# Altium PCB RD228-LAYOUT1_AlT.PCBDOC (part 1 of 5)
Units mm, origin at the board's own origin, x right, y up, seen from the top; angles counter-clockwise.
Board outline 130 x 73 mm, 4 copper layers (TOP, Mid-Layer 1, Mid-Layer 2, BOTTOM), stack 0.711 mm thick; 225 components, 171 nets, 818 pads, 538 vias.
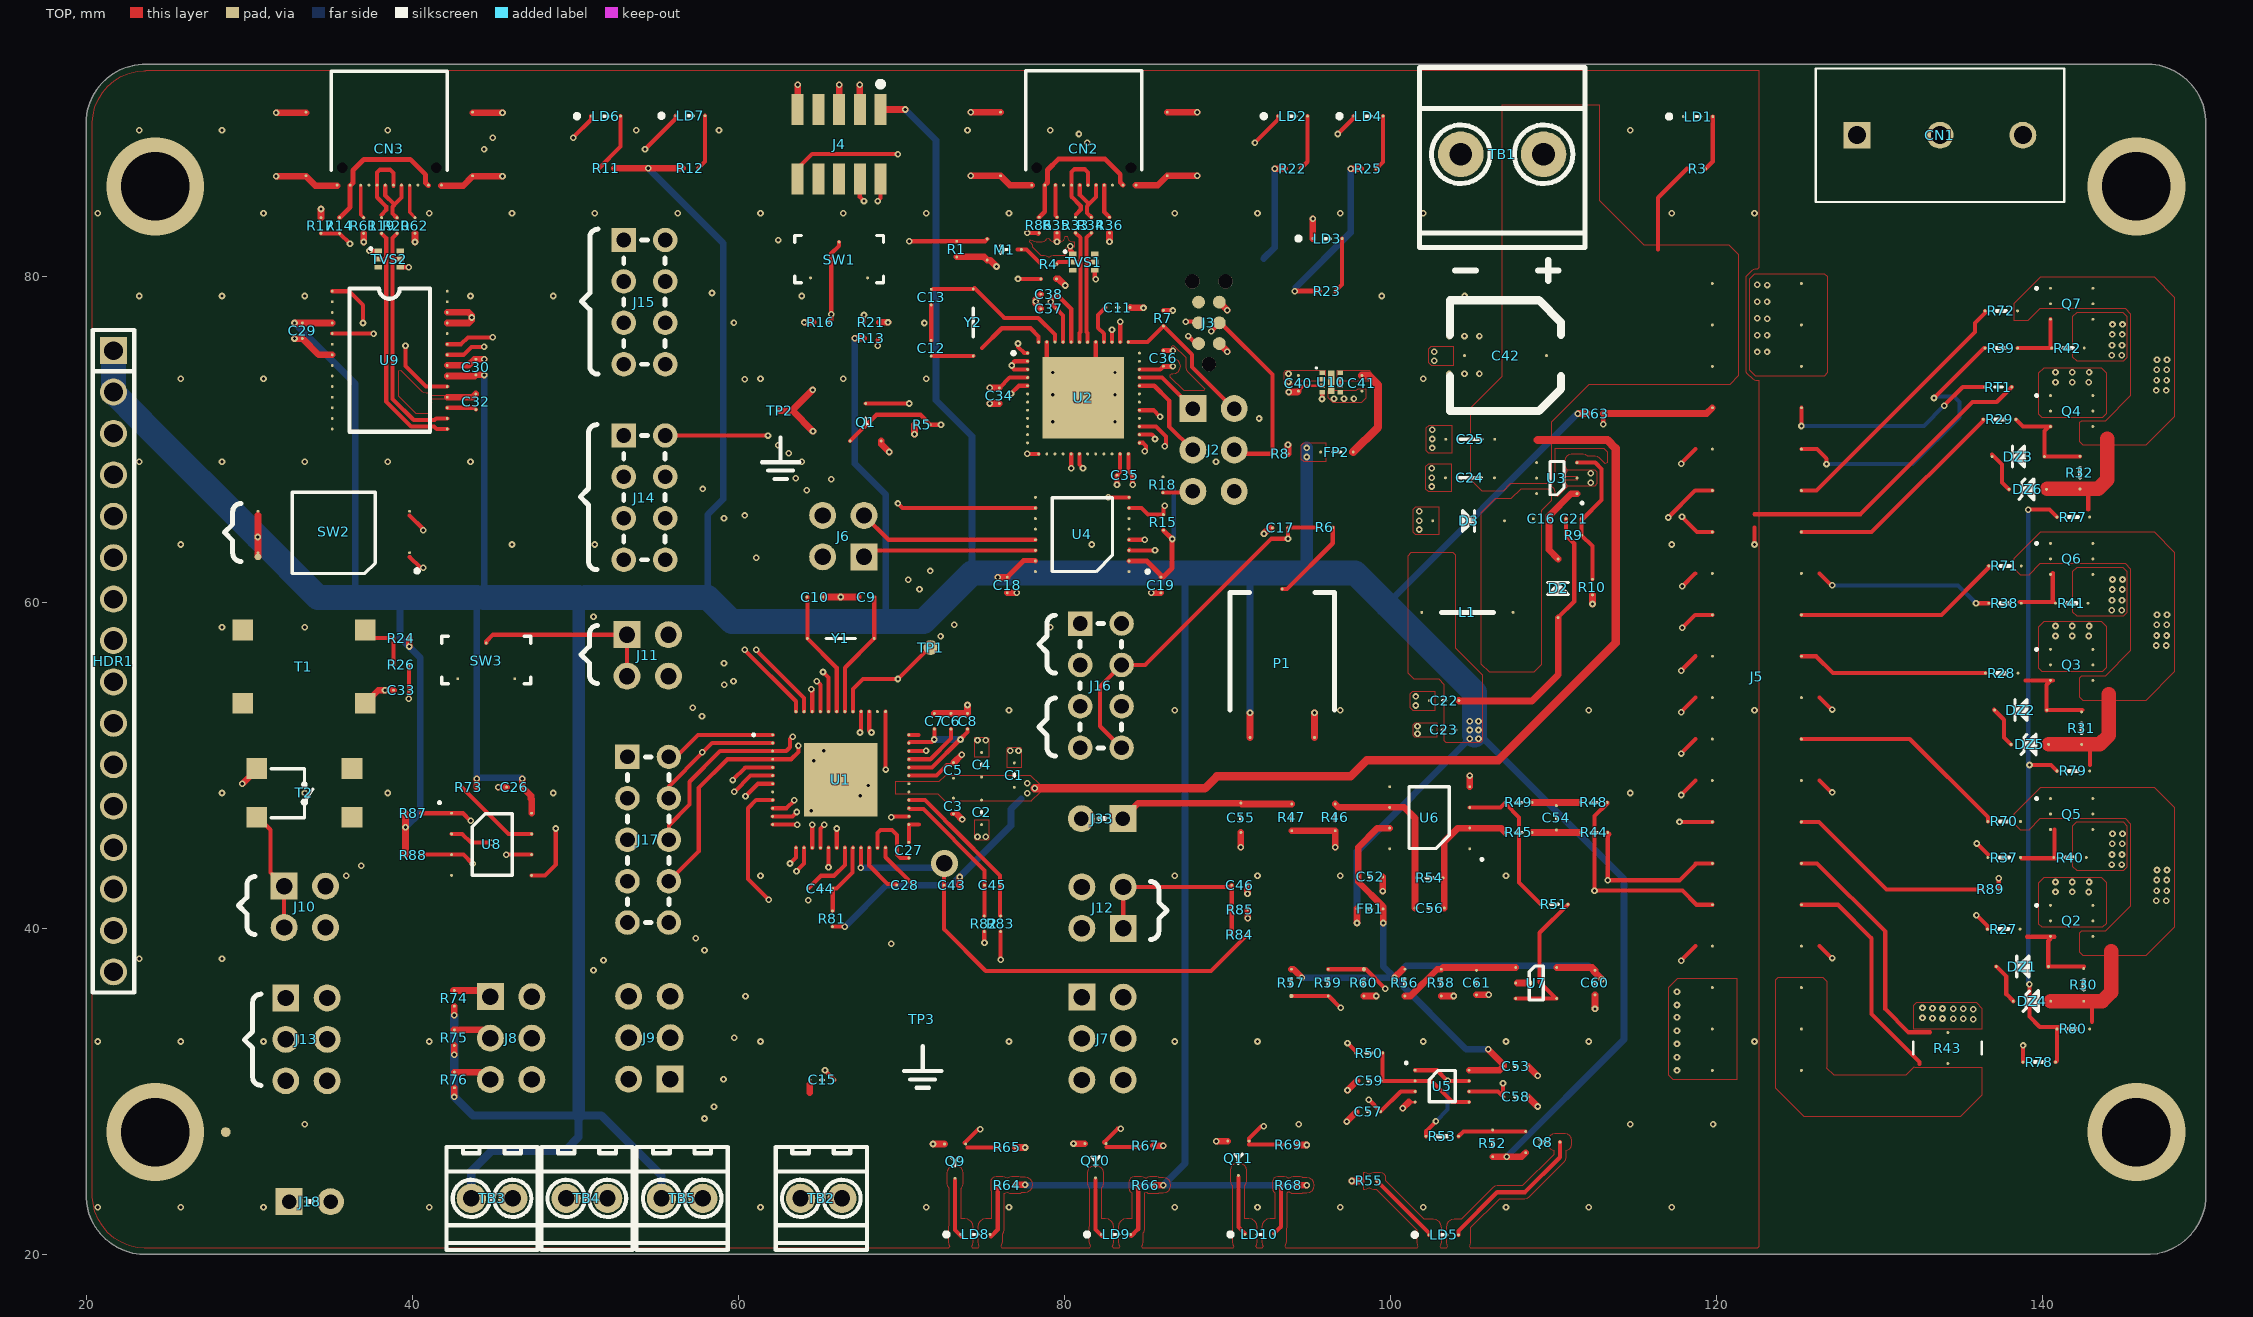
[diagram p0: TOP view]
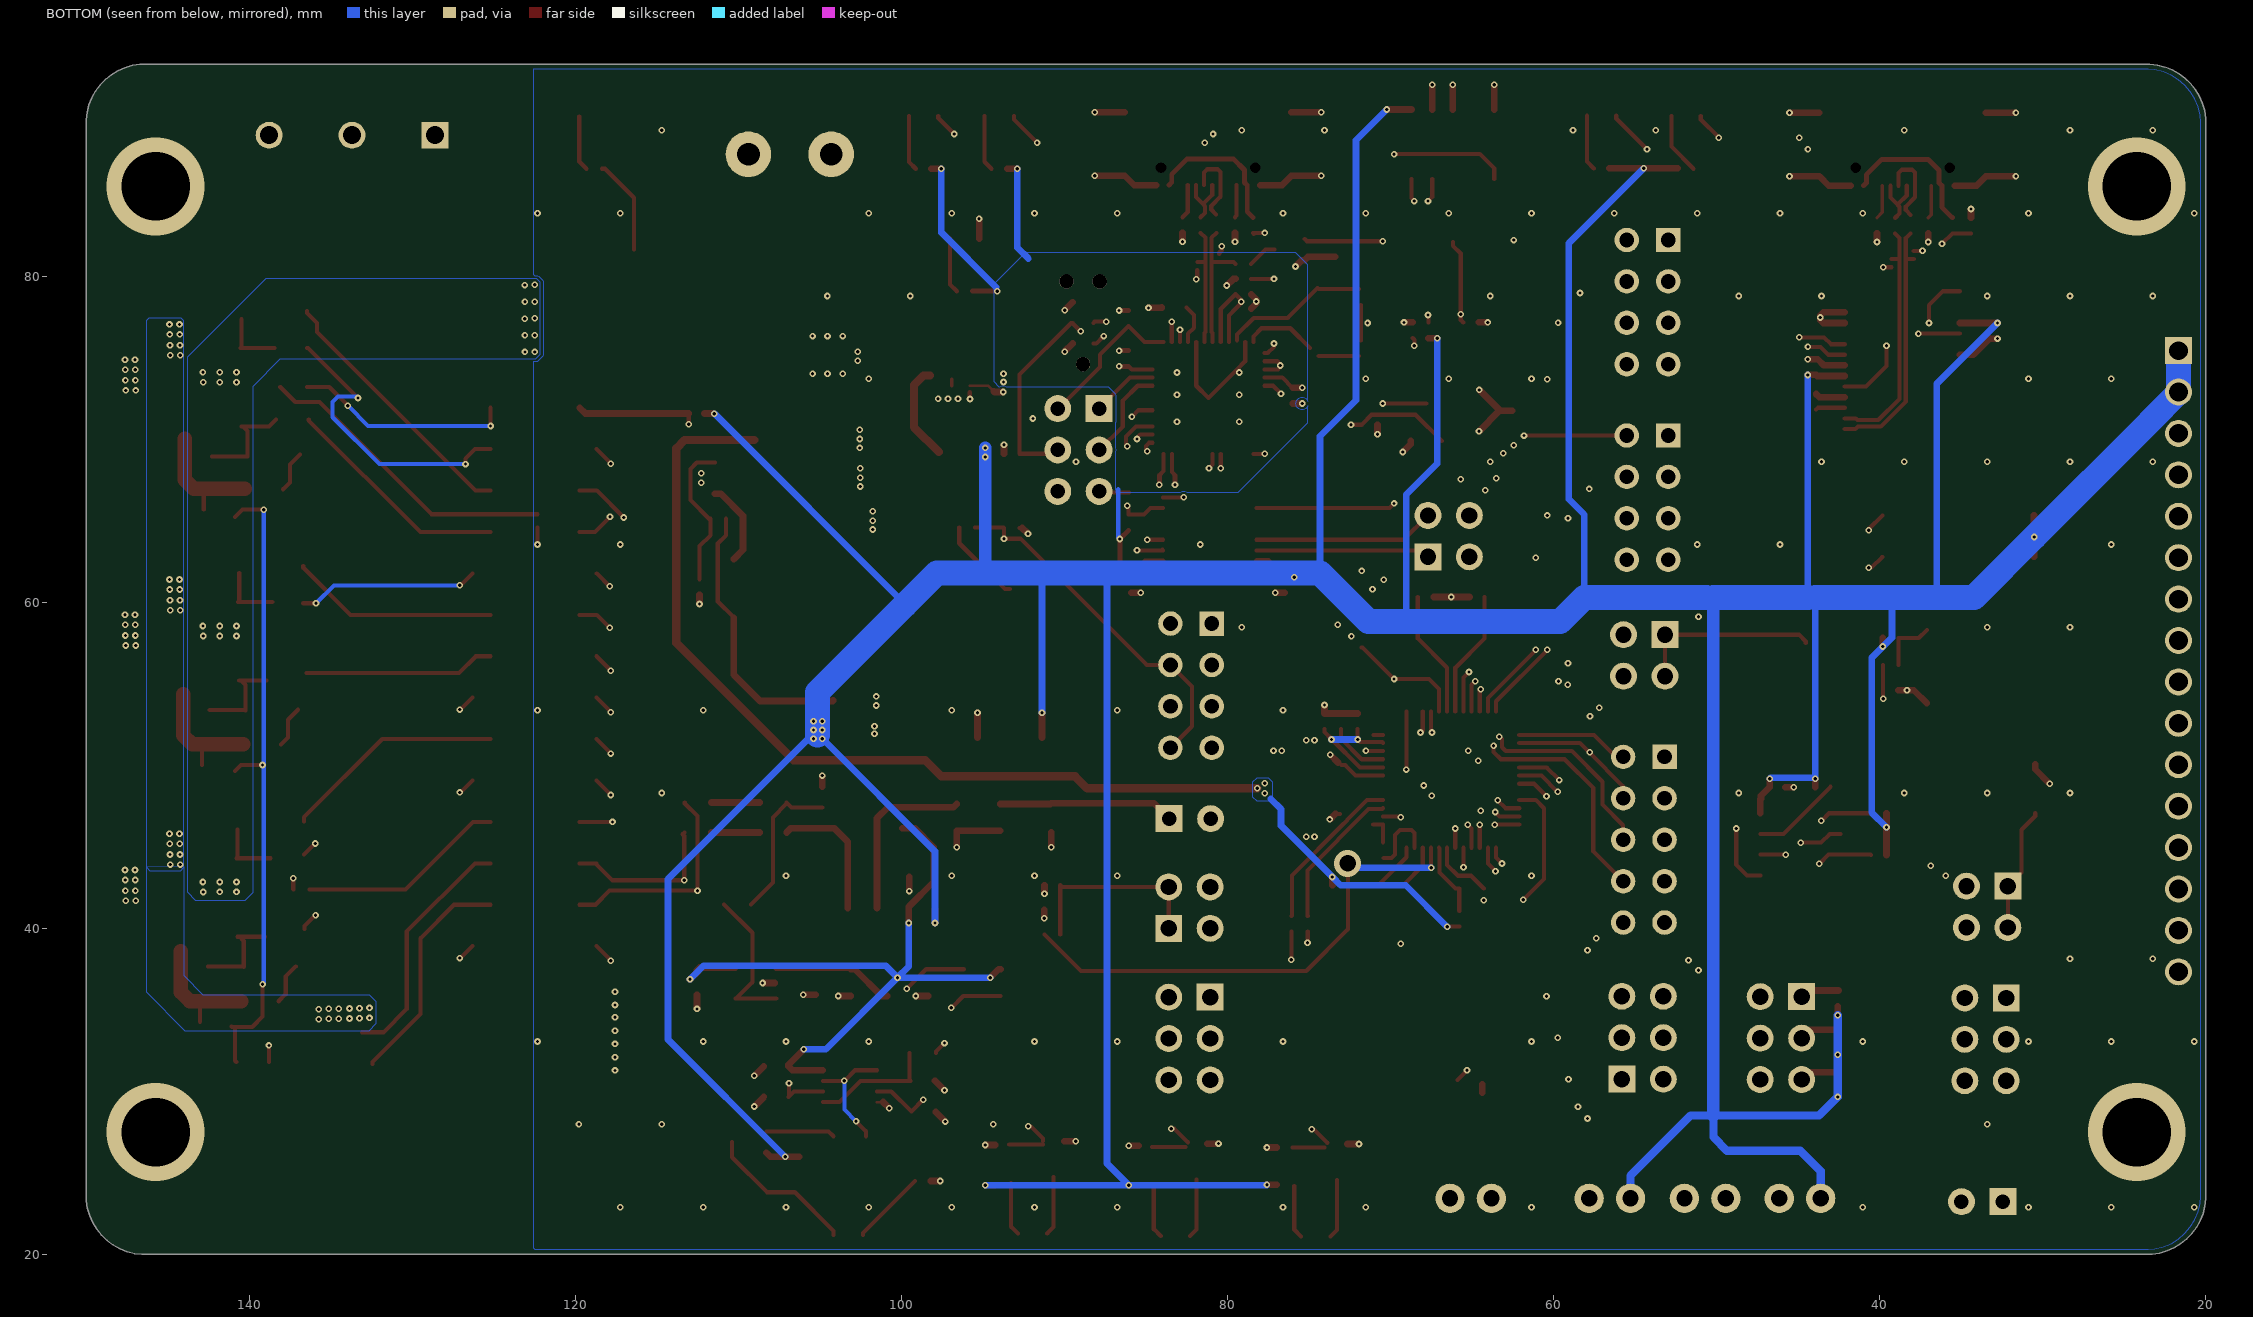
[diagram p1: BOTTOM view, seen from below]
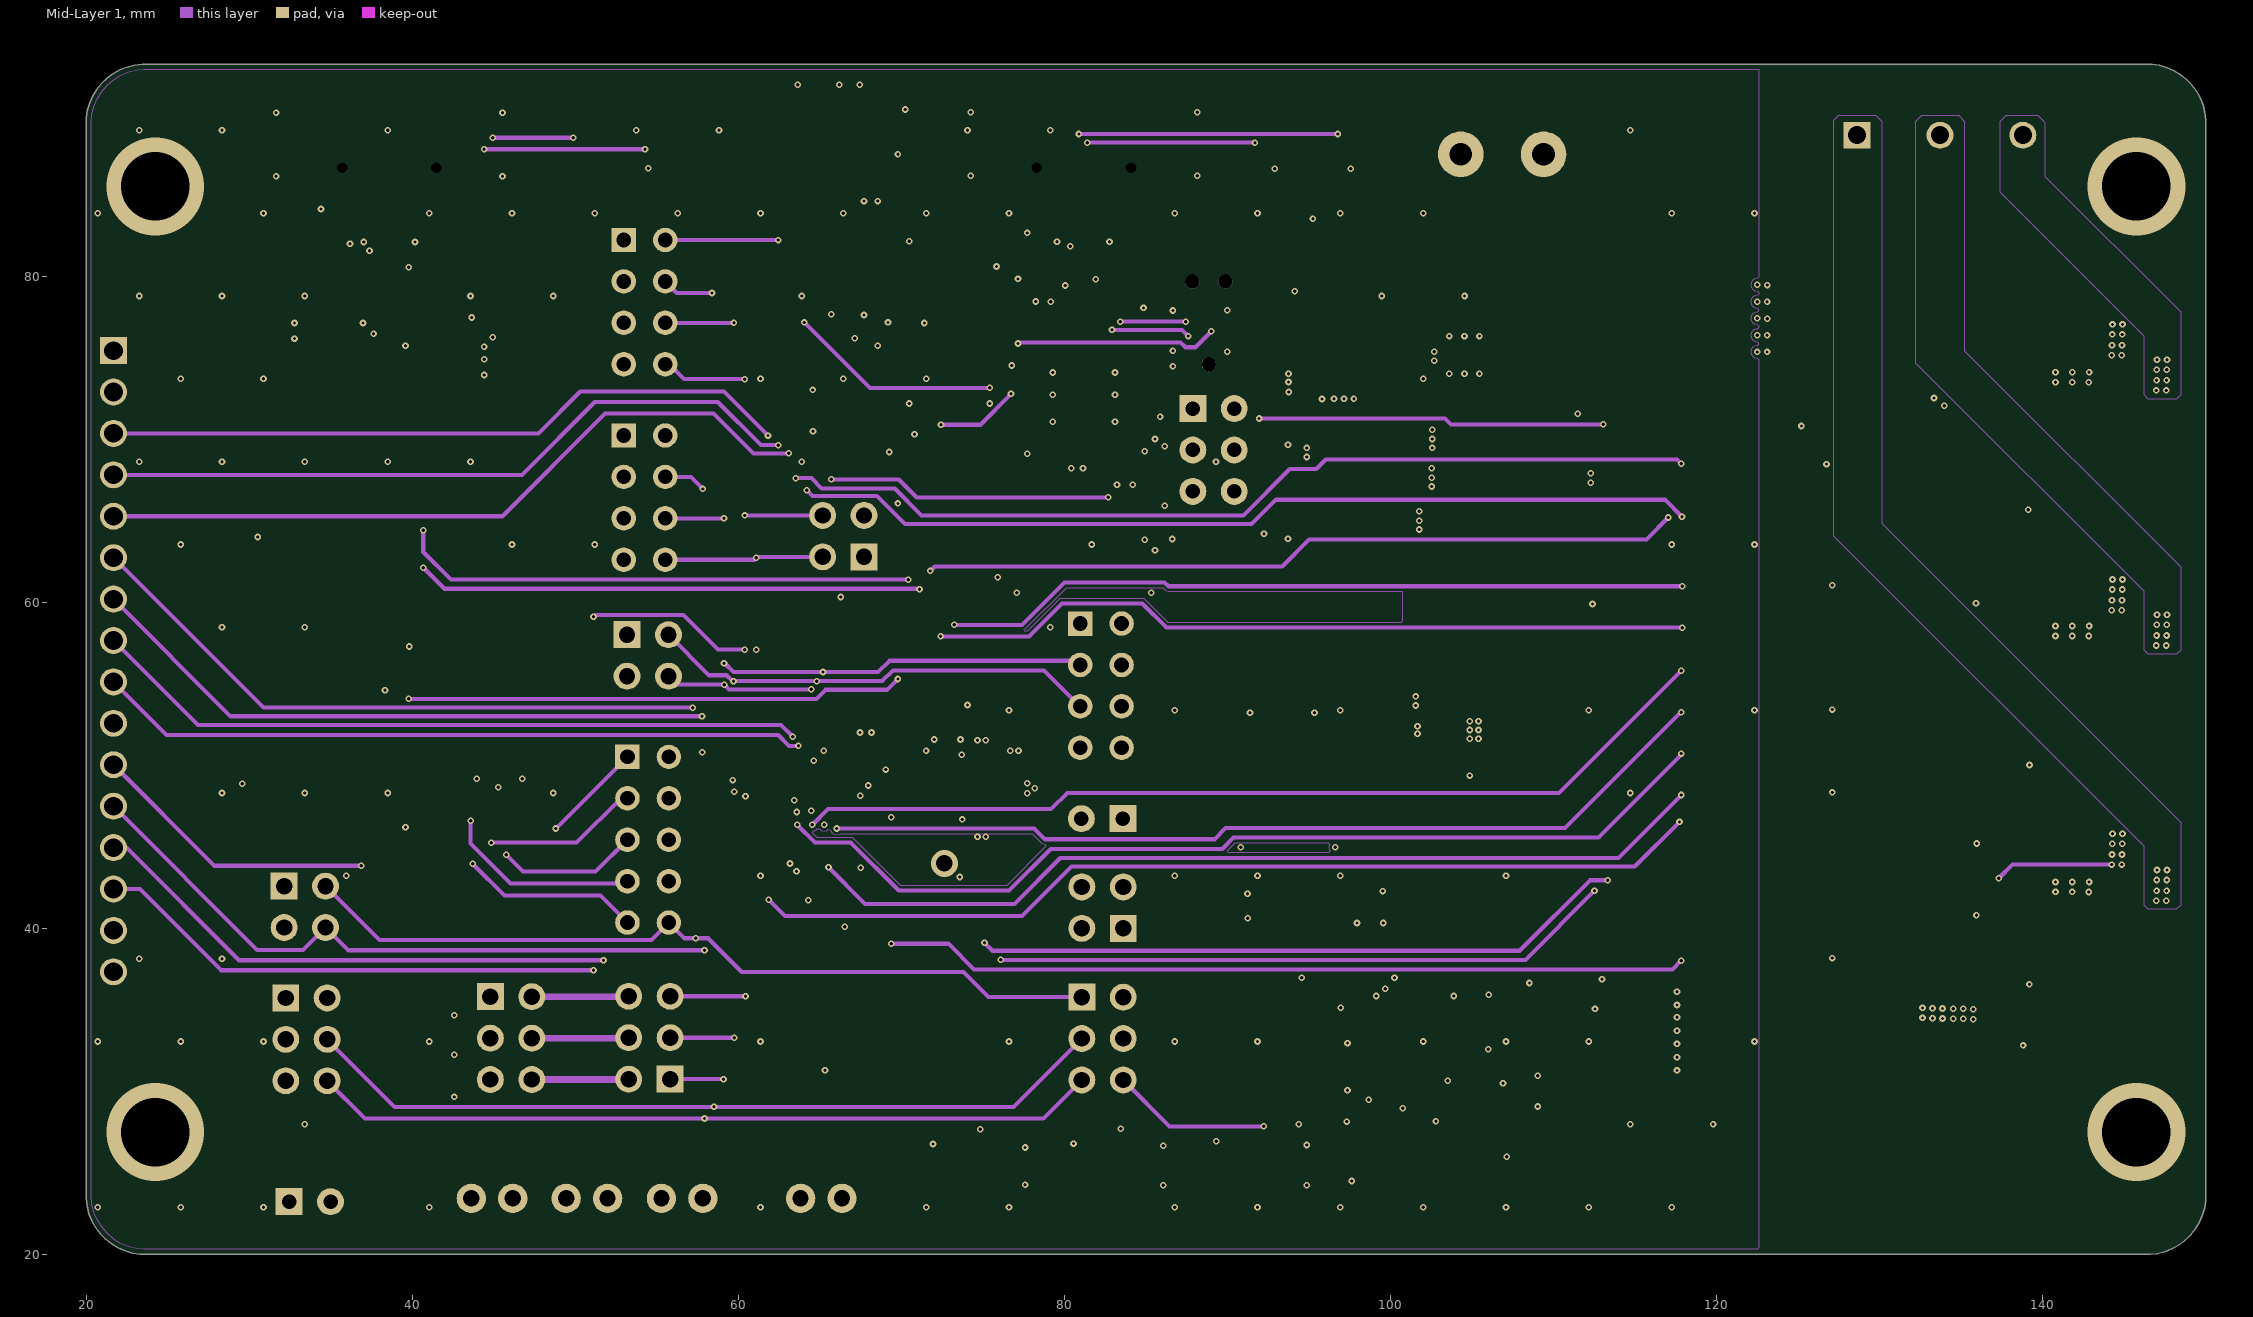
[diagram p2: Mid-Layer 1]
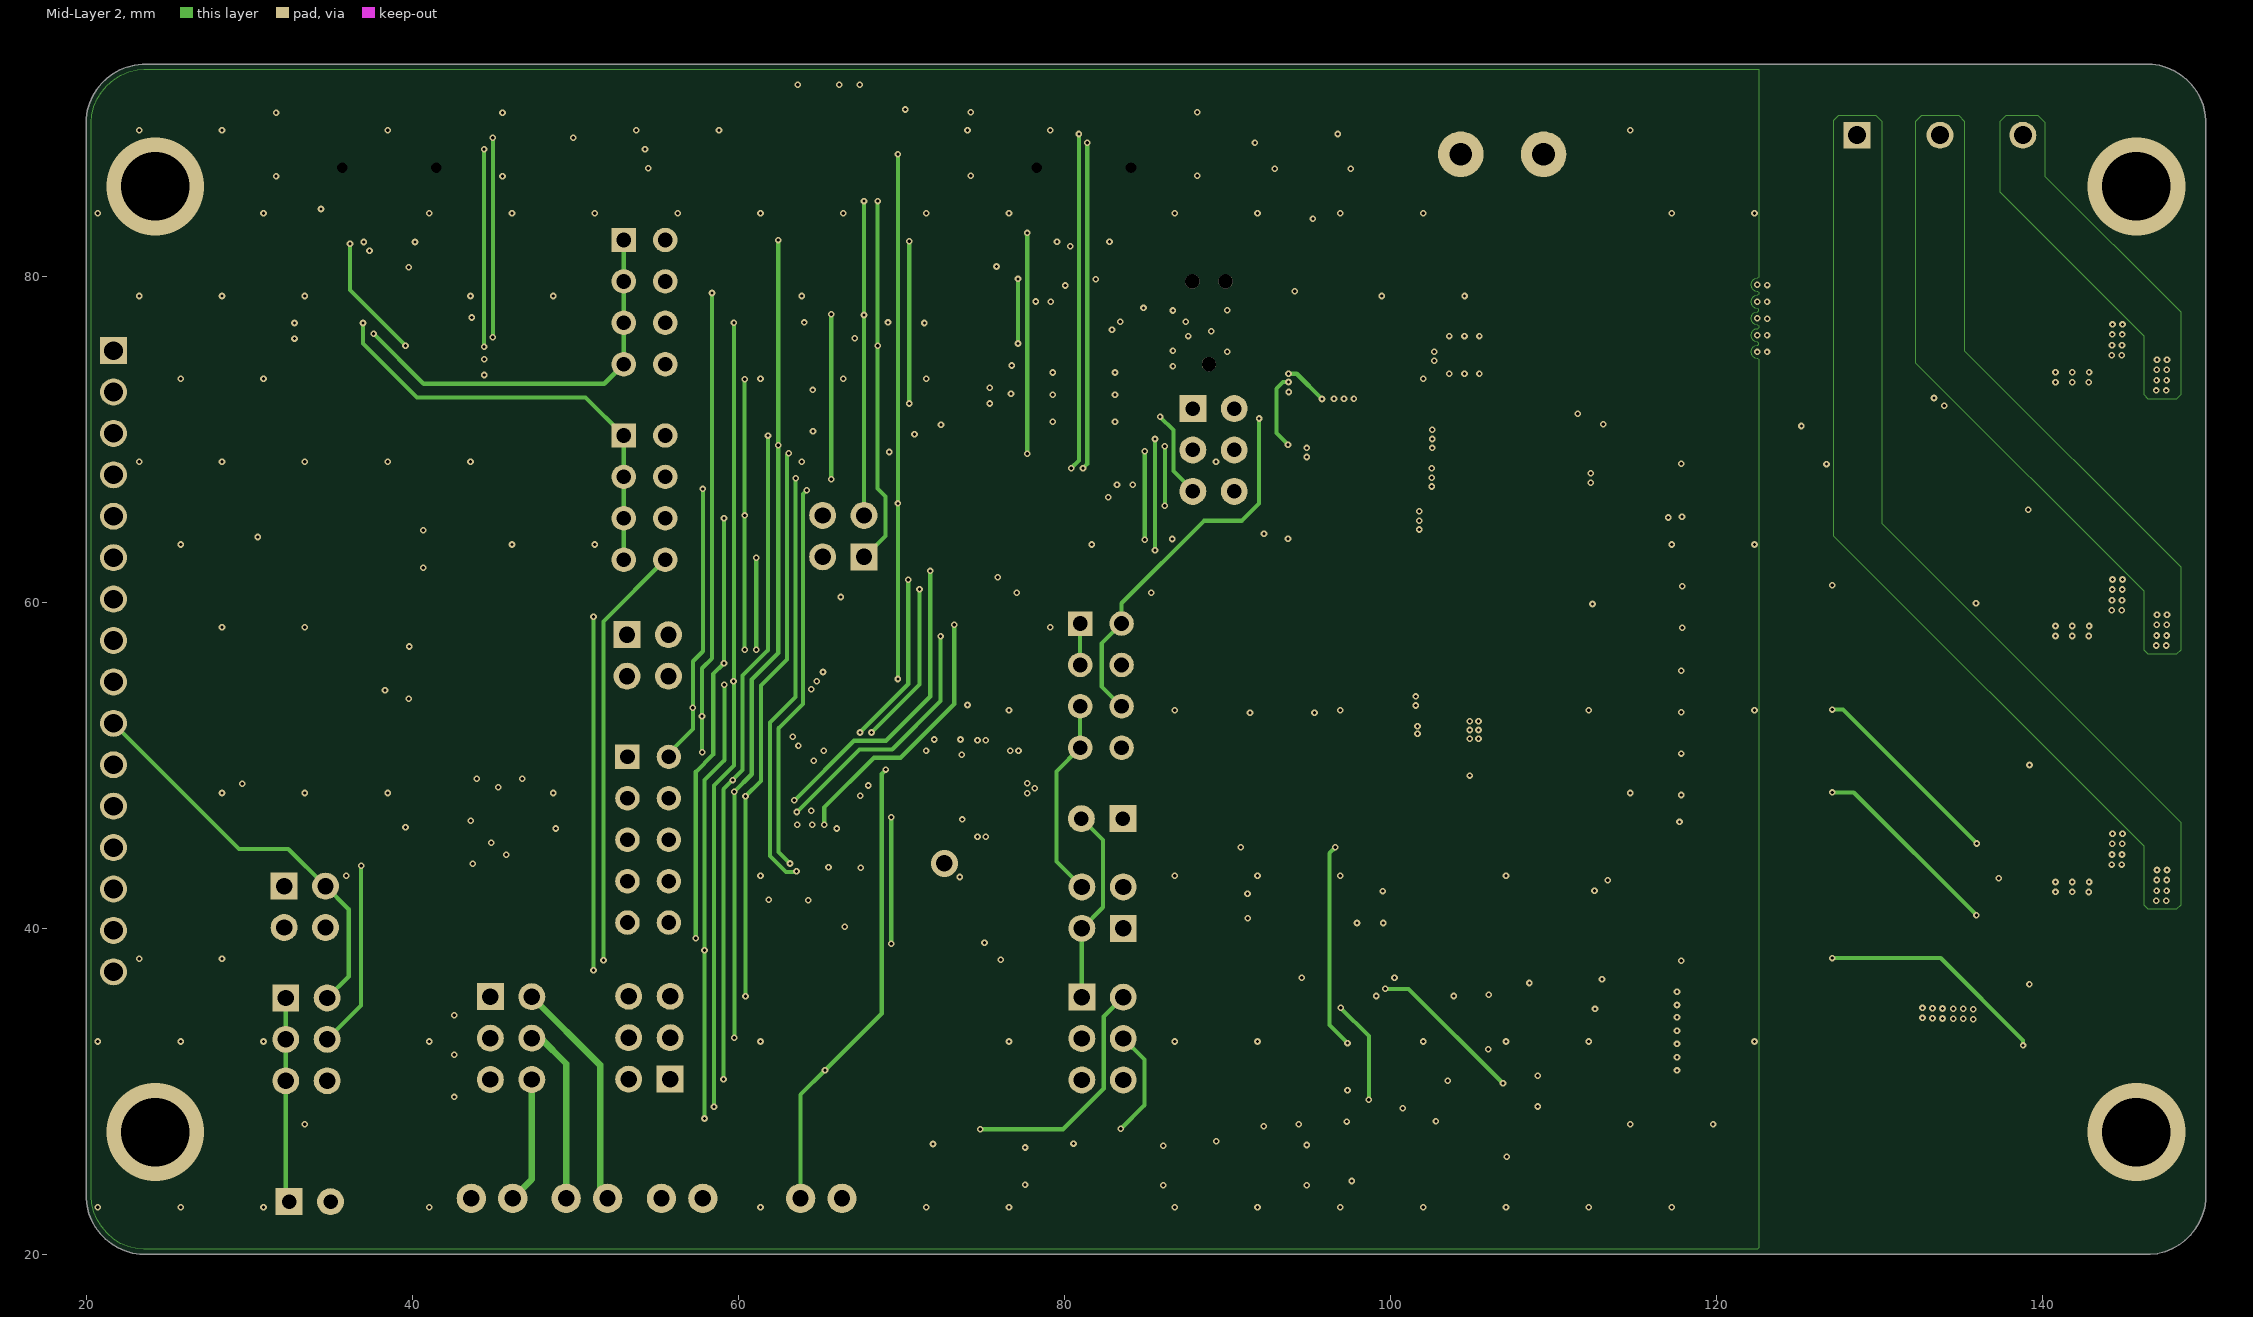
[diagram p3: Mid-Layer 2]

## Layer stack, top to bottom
Top Solder: solder mask 0.0102, Solder Resist, Dk 3.5
TOP: signal copper (thickness not stored)
Mid-Layer 1: signal copper 0.0356
Dielectric2: dielectric 0.32, FR-4, Dk 4.8
Mid-Layer 2: signal copper 0.0356
Dielectric3: dielectric 0.32, FR-4, Dk 4.8
BOTTOM: signal copper (thickness not stored)
Bottom Solder: solder mask 0.0102, Solder Resist, Dk 3.5

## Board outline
146.571,20 146.336,20.001 23.542,20.002 23.307,20.009 22.842,20.083 22.39,20.217 21.959,20.407 21.557,20.651 21.189,20.945 20.861,21.284 20.581,21.662 20.351,22.073 20.175,22.51 20.058,22.966 20,23.433 20.001,23.669 20.001,89.454 20.009,89.69 20.084,90.156 20.217,90.607 20.407,91.038 20.651,91.441 20.945,91.809 21.284,92.136 21.662,92.417 22.073,92.647 22.51,92.822 22.966,92.939 23.434,92.997 23.669,92.996 146.462,93.002 146.697,92.996 147.162,92.921 147.614,92.788 148.045,92.598 148.447,92.353 148.815,92.059 149.142,91.721 149.423,91.343 149.653,90.932 149.828,90.495 149.946,90.039 150.004,89.571 150.003,89.336 150.001,23.544 149.996,23.307 149.921,22.842 149.788,22.39 149.598,21.959 149.354,21.557 149.06,21.189 148.721,20.861 148.343,20.581 147.932,20.351 147.495,20.175 147.039,20.058

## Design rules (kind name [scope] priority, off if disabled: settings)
AssemblyTestPointUsage [All] p0: scope1count=1 scope1_0_kind=Board scope1_0_value=Board scope2count=1 scope2_0_kind=Board scope2_0_value=Board commentlength=0
AssemblyTestpoint [All] p0: scope1count=1 scope1_0_kind=Board scope1_0_value=Board scope2count=1 scope2_0_kind=Board scope2_0_value=Board commentlength=0
Clearance [All] p0: scope1count=1 scope1_0_kind=Board scope1_0_value=Board scope2count=1 scope2_0_kind=Board scope2_0_value=Board commentlength=0 gap=0.001
Clearance [All] p1: gap=0.001 ignorepadtopadclearanceinfootprint=TRUE except(0.15: Arc-Arc Arc-Track Arc-SMDPad Arc-THPad Arc-Via Arc-Fill Arc-Poly Arc-Region Arc-Text Track-Track Track-SMDPad Track-THPad Track-Via Track-Fill Track-Poly Track-Region Track-Text SMDPad-SMDPad SMDPad-THPad SMDPad-Via SMDPad-Fill SMDPad-Poly SMDPad-Region SMDPad-Text THPad-THPad THPad-Via THPad-Fill THPad-Poly THPad-Region THPad-Text Via-Via Via-Fill Via-Poly Via-Region Via-Text Fill-Fill Fill-Poly Fill-Region Fill-Text Poly-Poly Poly-Region Poly-Text Region-Region Region-Text Text-Text; 0.3: Arc-Hole Track-Hole SMDPad-Hole THPad-Hole Via-Hole Fill-Hole Poly-Hole Region-Hole Text-Hole)
ComponentClearance [All] p0: scope1count=1 scope1_0_kind=Board scope1_0_value=Board scope2count=1 scope2_0_kind=Board scope2_0_value=Board commentlength=0 gap=0.254 collisioncheckmode=3
DiffPairsRouting [All] p0: scope1count=1 scope1_0_kind=Board scope1_0_value=Board scope2count=1 scope2_0_kind=Board scope2_0_value=Board commentlength=0
FabricationTestPointUsage [All] p0: scope1count=1 scope1_0_kind=Board scope1_0_value=Board scope2count=1 scope2_0_kind=Board scope2_0_value=Board commentlength=0 valid=0 allowmultiple=FALSE
FabricationTestpoint [All] p0: scope1count=1 scope1_0_kind=Board scope1_0_value=Board scope2count=1 scope2_0_kind=Board scope2_0_value=Board commentlength=0 side=3 testpointundercomponent=TRUE minsize=1.016 maxsize=2.54 preferedsize=1.524 minholesize=0 maxholesize=1.016 preferedholesize=0.813 testpointgrid=0.025
FanoutControl Fanout_Default [All] p0: scope1count=1 scope1_0_kind=Board scope1_0_value=Board scope2count=1 scope2_0_kind=Board scope2_0_value=Board commentlength=30 // Fanout_Default (Default Rule)
FanoutControl Fanout_Small [All] p0 off: scope1count=1 scope1_0_kind=Board scope1_0_value=Board scope2count=1 scope2_0_kind=Board scope2_0_value=Board commentlength=84 // Protel DXP Scope 1 Expression Was: (CompPinCount < 5)   Fanout_Small (Default Rule)
FanoutControl Fanout_SOIC [All] p0 off: scope1count=1 scope1_0_kind=Board scope1_0_value=Board scope2count=1 scope2_0_kind=Board scope2_0_value=Board commentlength=71 // Protel DXP Scope 1 Expression Was: IsSOIC   Fanout_SOIC (Default Rule)
FanoutControl Fanout_LCC [All] p0 off: scope1count=1 scope1_0_kind=Board scope1_0_value=Board scope2count=1 scope2_0_kind=Board scope2_0_value=Board commentlength=69 // Protel DXP Scope 1 Expression Was: IsLCC   Fanout_LCC (Default Rule)
FanoutControl Fanout_BGA [All] p0 off: scope1count=1 scope1_0_kind=Board scope1_0_value=Board scope2count=1 scope2_0_kind=Board scope2_0_value=Board commentlength=69 // Protel DXP Scope 1 Expression Was: IsBGA   Fanout_BGA (Default Rule)
Height [All] p0: scope1count=1 scope1_0_kind=Board scope1_0_value=Board scope2count=1 scope2_0_kind=Board scope2_0_value=Board commentlength=0
HoleSize [All] p0: scope1count=1 scope1_0_kind=Board scope1_0_value=Board scope2count=1 scope2_0_kind=Board scope2_0_value=Board commentlength=0 absolutevalues=TRUE maxlimit=100 minlimit=0.001 maxpercent=80.000 minpercent=20.000
HoleSize [All] p1: absolutevalues=TRUE maxlimit=100 minlimit=0.001 maxpercent=80.000 minpercent=20.000
HoleToHoleClearance [All] p0: scope1count=1 scope1_0_kind=Board scope1_0_value=Board scope2count=1 scope2_0_kind=Board scope2_0_value=Board commentlength=0
HoleToHoleClearance [All] p1: gap=0.4 allowstackedmicrovias=FALSE
LayerPairs [All] p0: scope1count=1 scope1_0_kind=Board scope1_0_value=Board scope2count=1 scope2_0_kind=Board scope2_0_value=Board commentlength=0 enforce=TRUE
MinimumSolderMaskSliver [All] p0: scope1count=1 scope1_0_kind=Board scope1_0_value=Board scope2count=1 scope2_0_kind=Board scope2_0_value=Board commentlength=0
MinimumSolderMaskSliver [All] p1: minsoldermaskwidth=0.1
NetAntennae [All] p0: scope1count=1 scope1_0_kind=Board scope1_0_value=Board scope2count=1 scope2_0_kind=Board scope2_0_value=Board commentlength=0
NetAntennae [All] p1: netantennaetolerance=100
PasteMaskExpansion [All] p0: scope1count=1 scope1_0_kind=Board scope1_0_value=Board scope2count=1 scope2_0_kind=Board scope2_0_value=Board commentlength=0 expansion=0
PlaneClearance [All] p0: scope1count=1 scope1_0_kind=Board scope1_0_value=Board scope2count=1 scope2_0_kind=Board scope2_0_value=Board commentlength=0 clearance=0.001
PlaneClearance [All] p1: clearance=0.001
PlaneConnect [All] p0: scope1count=1 scope1_0_kind=Board scope1_0_value=Board scope2count=1 scope2_0_kind=Board scope2_0_value=Board commentlength=0 planeconnectstyle=Direct reliefexpansion=0.508 reliefentries=4 reliefconductorwidth=0.254 reliefairgap=0.254
PlaneConnect [All] p1: planeconnectstyle=Direct reliefexpansion=0.508 reliefentries=4 reliefconductorwidth=0.254 reliefairgap=0.254
PolygonConnect [All] p0: scope1count=1 scope1_0_kind=Board scope1_0_value=Board scope2count=1 scope2_0_kind=Board scope2_0_value=Board commentlength=0 connectstyle=Direct reliefconductorwidth=0.254 reliefentries=4 polygonreliefangle="90 Angle"
PolygonConnect [All] p1: connectstyle=Direct reliefconductorwidth=0.254 reliefentries=4 polygonreliefangle="90 Angle" airgapwidth=0.254
RoutingCorners [All] p0: scope1count=1 scope1_0_kind=Board scope1_0_value=Board scope2count=1 scope2_0_kind=Board scope2_0_value=Board commentlength=0 cornerstyle=45-Degree minsetback=2.54 maxsetback=2.54
RoutingLayers [All] p0: scope1count=1 scope1_0_kind=Board scope1_0_value=Board scope2count=1 scope2_0_kind=Board scope2_0_value=Board commentlength=0 top layer=Automatic mid layer 1=Automatic mid layer 2=Automatic bottom layer=Automatic
RoutingPriority [All] p0: scope1count=1 scope1_0_kind=Board scope1_0_value=Board scope2count=1 scope2_0_kind=Board scope2_0_value=Board commentlength=0
RoutingTopology [All] p0: scope1count=1 scope1_0_kind=Board scope1_0_value=Board scope2count=1 scope2_0_kind=Board scope2_0_value=Board commentlength=0 topology=Shortest
RoutingVias [All] p0: scope1count=1 scope1_0_kind=Board scope1_0_value=Board scope2count=1 scope2_0_kind=Board scope2_0_value=Board commentlength=0 holewidth=0.1 width=0.1 viastyle="Through Hole" minholewidth=0.001 minwidth=0.001 maxholewidth=100 maxwidth=100
RoutingVias [All] p1: holewidth=0.1 width=0.1 viastyle="Through Hole" minholewidth=0.001 minwidth=0.001 maxholewidth=100 maxwidth=100
ShortCircuit [All] p0: scope1count=1 scope1_0_kind=Board scope1_0_value=Board scope2count=1 scope2_0_kind=Board scope2_0_value=Board commentlength=0 allowed=FALSE
ShortCircuit [All] p0: scope1count=1 scope1_0_kind=Board scope1_0_value=Board scope2count=1 scope2_0_kind=Board scope2_0_value=Board commentlength=0 allowed=FALSE
SilkToBoardRegionClearance [All] p0: scope1count=1 scope1_0_kind=Board scope1_0_value=Board scope2count=1 scope2_0_kind=Board scope2_0_value=Board commentlength=0
SilkToSilkClearance [All] p0: scope1count=1 scope1_0_kind=Board scope1_0_value=Board scope2count=1 scope2_0_kind=Board scope2_0_value=Board commentlength=0
SilkToSilkClearance [All] p1: silktosilkclearance=0.001
SilkToSolderMaskClearance [All] p0 off: scope1count=1 scope1_0_kind=Board scope1_0_value=Board scope2count=1 scope2_0_kind=Board scope2_0_value=Board commentlength=44 // Protel DXP Scope 1 Expression Was: IsPad
SilkToSolderMaskClearance [IsPad] p1: minsilkscreentomaskgap=0 clearancetoexposedcopper=TRUE
SolderMaskExpansion [All] p0: scope1count=1 scope1_0_kind=Board scope1_0_value=Board scope2count=1 scope2_0_kind=Board scope2_0_value=Board commentlength=0 expansion=0.001
SolderMaskExpansion [All] p1: expansion=0.001
UnRoutedNet [All] p0: scope1count=1 scope1_0_kind=Board scope1_0_value=Board scope2count=1 scope2_0_kind=Board scope2_0_value=Board commentlength=0
UnpouredPolygon [All] p0: scope1count=1 scope1_0_kind=Board scope1_0_value=Board scope2count=1 scope2_0_kind=Board scope2_0_value=Board commentlength=0
Width [All] p0: scope1count=1 scope1_0_kind=Board scope1_0_value=Board scope2count=1 scope2_0_kind=Board scope2_0_value=Board commentlength=0 maxlimit=1000 minlimit=2539.975 preferedwidth=0
Width [All] p1: maxlimit=1000 minlimit=2539.975 preferedwidth=0 toplayer_minwidth=0 midlayer1_minwidth=0 midlayer2_minwidth=0 bottomlayer_minwidth=0 minimp=50.000000 maximp=50.000000 favimp=50.000000
22 further rules are at their usual default settings.

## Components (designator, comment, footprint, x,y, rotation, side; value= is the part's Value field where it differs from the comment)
C1 "CAPC1608X55N-0603-NoOverlay" CAPC1608X55N-0603-NoOverlay 76.925,49.397 r0 top
C2 "CAPC1608X55N-0603-NoOverlay" CAPC1608X55N-0603-NoOverlay 74.919,47.111 r180 top
C3 "CAPC1005X55N-0402-NoOverlay" CAPC1005X55N-0402-NoOverlay 73.191,47.502 r180 top
C4 "CAPC1608X55N-0603-NoOverlay" CAPC1608X55N-0603-NoOverlay 74.919,50.032 r0 top
C5 "CAPC1005X55N-0402-NoOverlay" CAPC1005X55N-0402-NoOverlay 73.195,49.687 r0 top
C6 "CAPC1005X55N-0402-NoOverlay" CAPC1005X55N-0402-NoOverlay 73.039,52.699 r0 top
C7 "CAPC1005X55N-0402-NoOverlay" CAPC1005X55N-0402-NoOverlay 72.023,52.699 r0 top
C8 "CAPC1005X55N-0402-NoOverlay" CAPC1005X55N-0402-NoOverlay 74.055,52.699 r0 top
C9 "CAPC1005X55N-0402-NoOverlay" CAPC1005X55N-0402-NoOverlay 67.832,60.319 r90 top
C10 "CAPC1005X55N-0402-NoOverlay" CAPC1005X55N-0402-NoOverlay 64.682,60.319 r270 top
C11 "CAPC1608X55N-0603-NoOverlay" CAPC1608X55N-0603-NoOverlay 83.275,78.073 r270 top
C12 "CAPC1005X55N-0402-NoOverlay" CAPC1005X55N-0402-NoOverlay 71.828,75.575 r0 top
C13 "CAPC1005X55N-0402-NoOverlay" CAPC1005X55N-0402-NoOverlay 71.828,78.708 r180 top
C15 "CAPC1608X55N-0603-NoOverlay" CAPC1608X55N-0603-NoOverlay 65.14,30.702 r90 top
C16 "CAPC1005X55N-0402-NoOverlay" CAPC1005X55N-0402-NoOverlay 109.234,65.119 r90 top
C17 "CAPC1005X55N-0402-NoOverlay" CAPC1005X55N-0402-NoOverlay 93.232,64.561 r270 top
C18 "CAPC1005X55N-0402-NoOverlay" CAPC1005X55N-0402-NoOverlay 76.493,61.055 r0 top
C19 "CAPC1005X55N-0402-NoOverlay" CAPC1005X55N-0402-NoOverlay 85.917,61.055 r0 top
C21 "CAPC1005X55N-0402-NoOverlay" CAPC1005X55N-0402-NoOverlay 111.241,65.119 r270 top
C22 "CAPC2013X100N-0805-NoOverlay" CAPC2013X100N-0805-NoOverlay 103.29,53.969 r90 top
C23 "CAPC1608X55N-0603-NoOverlay" CAPC1608X55N-0603-NoOverlay 103.253,52.165 r270 top
C24 "CAPC3216X140N-1206-NoOverlay" CAPC3216X140N-1206-NoOverlay 104.865,67.63 r0 top
C25 "CAPC3216X140N-1206-NoOverlay" CAPC3216X140N-1206-NoOverlay 104.889,69.996 r0 top
C26 "CAPC1005X55N-0402-NoOverlay" CAPC1005X55N-0402-NoOverlay 46.27,48.66 r90 top
C27 "CAPC1005X55N-0402-NoOverlay" CAPC1005X55N-0402-NoOverlay 70.458,44.799 r0 top
C28 "CAPC1005X55N-0402-NoOverlay" CAPC1005X55N-0402-NoOverlay 70.197,42.645 r270 top
C29 "CAPC1005X55N-0402-NoOverlay" CAPC1005X55N-0402-NoOverlay 33.263,76.651 r0 top
C30 "CAPC1005X55N-0402-NoOverlay" CAPC1005X55N-0402-NoOverlay 43.905,74.423 r180 top
C32 "CAPC1005X55N-0402-NoOverlay" CAPC1005X55N-0402-NoOverlay 43.905,72.29 r180 top
C33 "CAPC1005X55N-0402-NoOverlay" CAPC1005X55N-0402-NoOverlay 39.333,54.604 r270 top
C34 "CAPC1005X55N-0402-NoOverlay" CAPC1005X55N-0402-NoOverlay 76.011,72.663 r0 top
C35 "CAPC1005X55N-0402-NoOverlay" CAPC1005X55N-0402-NoOverlay 83.707,67.786 r90 top
C36 "CAPC1005X55N-0402-NoOverlay" CAPC1005X55N-0402-NoOverlay 86.069,74.949 r180 top
C37 "CAPC1005X55N-0402-NoOverlay" CAPC1005X55N-0402-NoOverlay 79.033,77.997 r270 top
C38 "CAPC1005X55N-0402-NoOverlay" CAPC1005X55N-0402-NoOverlay 79.033,78.886 r270 top
C40 "CAPC1005X55N-0402-NoOverlay" CAPC1005X55N-0402-NoOverlay 94.35,73.425 r180 top
C41 "CAPC1005X55N-0402-NoOverlay" CAPC1005X55N-0402-NoOverlay 98.245,73.425 r180 top
C42 "CAPAE660X550D700DD185L260N" CAPAE660X550D700DD185L260N 107.05,75.127 r180 top
C43 "CAPC1005X55N-0402-NoOverlay" CAPC1005X55N-0402-NoOverlay 73.087,42.64 r90 top
C44 "CAPC1608X55N-0603-NoOverlay" CAPC1608X55N-0603-NoOverlay 65.038,42.437 r90 top
C45 "CAPC1005X55N-0402-NoOverlay" CAPC1005X55N-0402-NoOverlay 75.579,42.64 r270 top
C46 "CAPC1005X55N-0402-NoOverlay" CAPC1005X55N-0402-NoOverlay 90.743,42.64 r270 top
C52 "CAPC1608X55N-0603-NoOverlay" CAPC1608X55N-0603-NoOverlay 98.769,43.148 r270 top
C53 "CAPC1608X55N-0603-NoOverlay" CAPC1608X55N-0603-NoOverlay 107.685,31.541 r270 top
C54 "CAPC1608X55N-0603-NoOverlay" CAPC1608X55N-0603-NoOverlay 110.174,46.781 r0 top
C55 "CAPC2013X100N-0805-NoOverlay" CAPC2013X100N-0805-NoOverlay 90.819,46.781 r180 top
C56 "CAPC2013X100N-0805-NoOverlay" CAPC2013X100N-0805-NoOverlay 102.401,41.243 r90 top
C57 "CAPC1608X55N-0603-NoOverlay" CAPC1608X55N-0603-NoOverlay 98.642,28.763 r90 top
C58 "CAPC1608X55N-0603-NoOverlay" CAPC1608X55N-0603-NoOverlay 107.685,29.661 r270 top
C59 "CAPC1608X55N-0603-NoOverlay" CAPC1608X55N-0603-NoOverlay 98.693,30.652 r90 top
C60 "CAPC1608X55N-0603-NoOverlay" CAPC1608X55N-0603-NoOverlay 112.536,36.671 r180 top
C61 "CAPC1608X55N-0603-NoOverlay" CAPC1608X55N-0603-NoOverlay 105.272,36.671 r180 top
CN1 "SCREW_TERMINAL_3P_5.08" SCREW_TERMINAL_3P_5.08 133.694,88.64 r0 top
CN2 "USB-C_SMD_16P-NoOverlay_r1" USB-C_SMD_16P-NoOverlay_r1 81.192,87.776 r180 top
CN3 "USB-C_SMD_16P-NoOverlay_r1" USB-C_SMD_16P-NoOverlay_r1 38.597,87.776 r180 top
D2 "SOD3716X135N-NoOverlay" SOD3716X135N-NoOverlay 110.275,60.852 r270 top
D3 "DIOM5127X229N-SOD128-NoOverlay" DIOM5127X229N-SOD128-NoOverlay 104.789,64.992 r180 top
DZ1 "SFLAT300P360X150X100-2N" SFLAT300P360X150X100-2N 138.749,37.658 r0 top
DZ2 "SFLAT300P360X150X100-2N" SFLAT300P360X150X100-2N 138.647,53.381 r0 top
DZ3 "SFLAT300P360X150X100-2N" SFLAT300P360X150X100-2N 138.495,68.929 r0 top
DZ4 "XCUZ230P125X250X100-2N" XCUZ230P125X250X100-2N 139.34,35.532 r0 top
DZ5 "XCUZ230P125X250X100-2N" XCUZ230P125X250X100-2N 139.206,51.28 r0 top
DZ6 "XCUZ230P125X250X100-2N" XCUZ230P125X250X100-2N 139.079,66.924 r0 top
FB1 "INDC1608X95N-0603-NOOVERLAY" INDC1608X95N-0603-NOOVERLAY 98.744,41.193 r0 top
FP2 "INDC2213X140N-0805-NOOVERLAY" INDC2213X140N-0805-NOOVERLAY 96.712,69.209 r0 top
HDR1 "HM1X16_-_Male" HM1X16_-_Male 21.68,56.382 r0 top
J2 "JUMPER-FLD2X3" JUMPER-FLD2X3 87.873,71.876 r0 top
J3 "TC2030NL_r1" TC2030NL_r1 88.863,77.134 r90 top
J4 "HM2X5-SMD-1.27" HM2X5-SMD-1.27 66.181,88.09 r270 top
J5 "HM254P2x20-SMD" HM254P2x20-SMD 122.467,55.417 r0 top
J6 "HM2X2" HM2X2 66.439,64.053 r180 top
J7 "HM2X3" HM2X3 82.335,33.242 r0 top
J8 "HM2X3" HM2X3 46.064,33.268 r0 top
J9 "HM2X3" HM2X3 54.548,33.293 r180 top
J10 "HM2X2" HM2X2 33.415,41.32 r0 top
J11 "HM2X2" HM2X2 54.446,56.737 r0 top
J12 "HM2X2" HM2X2 82.335,41.269 r180 top
J13 "HM2X3" HM2X3 33.517,33.192 r0 top
J14 "HM2X4-NoOverlay" HM2X4-NoOverlay 54.243,66.415 r0 top
J15 "HM2X4-NoOverlay" HM2X4-NoOverlay 54.243,78.404 r0 top
J16 "HM2X4-NoOverlay" HM2X4-NoOverlay 82.234,54.883 r0 top
J17 "HM2X5-NoOverlay" HM2X5-NoOverlay 54.472,45.434 r0 top
J18 "HM1x2-NoOverlay" HM1x2-NoOverlay 33.72,23.235 r0 top
J33 "HM1x2-NoOverlay" HM1x2-NoOverlay 82.31,46.73 r180 top
L1 "IND_8x8x4-NoOverlay" IND_8x8x4-NoOverlay 104.713,59.379 r180 top
LD1 "DIOGREENC2013X120N-0805-NoOverlay" DIOGREENC2013X120N-0805-NoOverlay 118.861,89.783 r270 top
LD2 "DIOGREENC2013X120N-0805-NoOverlay" DIOGREENC2013X120N-0805-NoOverlay 94.005,89.808 r270 top
LD3 "DIOGREENC2013X120N-0805-NoOverlay" DIOGREENC2013X120N-0805-NoOverlay 96.128,82.3 r270 top
LD4 "DIOGREENC2013X120N-0805-NoOverlay" DIOGREENC2013X120N-0805-NoOverlay 98.642,89.808 r270 top
LD5 "DIOREDC2013X120N-0805-NoOverlay" DIOREDC2013X120N-0805-NoOverlay 103.265,21.203 r0 top
LD6 "DIOYELLOWC2013X120N-0805-NoOverlay" DIOYELLOWC2013X120N-0805-NoOverlay 51.881,89.808 r0 top
LD7 "DIOREDC2013X120N-0805-NoOverlay" DIOREDC2013X120N-0805-NoOverlay 57.062,89.834 r0 top
LD8 "DIOREDC2013X120N-0805-NoOverlay" DIOREDC2013X120N-0805-NoOverlay 74.538,21.228 r0 top
LD9 "DIOREDC2013X120N-0805-NoOverlay" DIOREDC2013X120N-0805-NoOverlay 83.165,21.228 r0 top
LD10 "DIOREDC2013X120N-0805-NoOverlay" DIOREDC2013X120N-0805-NoOverlay 91.962,21.228 r0 top
M1 "SOT65P210X100-3N-NoOverlay" SOT65P210X100-3N-NoOverlay 76.313,81.629 r0 top
P1 "N6R" N6R 93.359,56.255 r0 top
Q1 "SOT95P240X110-3N-NoOverlay" SOT95P240X110-3N-NoOverlay 67.811,71.038 r90 top
Q2 "TSOP6F95P220X290X80-6N" TSOP6F95P220X290X80-6N 141.772,40.459 r270 top
Q3 "TSOP6F95P220X290X80-6N" TSOP6F95P220X290X80-6N 141.772,56.157 r270 top
Q4 "TSOP6F95P220X290X80-6N" TSOP6F95P220X290X80-6N 141.772,71.724 r270 top
Q5 "TSOP6F95P220X290X80-6N" TSOP6F95P220X290X80-6N 141.772,47.01 r270 top
Q6 "TSOP6F95P220X290X80-6N" TSOP6F95P220X290X80-6N 141.772,62.656 r270 top
Q7 "TSOP6F95P220X290X80-6N" TSOP6F95P220X290X80-6N 141.772,78.302 r270 top
Q8 "SOT65P210X100-3N-NoOverlay" SOT65P210X100-3N-NoOverlay 109.336,26.892 r0 top
Q9 "SOT65P210X100-3N-NoOverlay" SOT65P210X100-3N-NoOverlay 73.293,25.724 r270 top
Q10 "SOT65P210X100-3N-NoOverlay" SOT65P210X100-3N-NoOverlay 81.904,25.749 r270 top
Q11 "SOT65P210X100-3N-NoOverlay" SOT65P210X100-3N-NoOverlay 90.667,25.902 r270 top
R1 "RESC1005X40N-0402-NOOVERLAY" RESC1005X40N-0402-NOOVERLAY 73.395,81.657 r180 top
R3 "RESC1005X40N-0402-NOOVERLAY" RESC1005X40N-0402-NOOVERLAY 118.835,86.582 r270 top
R4 "RESC1005X40N-0402-NOOVERLAY" RESC1005X40N-0402-NOOVERLAY 79.033,80.74 r270 top
R5 "RESC1005X40N-0402-NOOVERLAY" RESC1005X40N-0402-NOOVERLAY 71.286,70.885 r90 top
R6 "RESC1005X40N-0402-NOOVERLAY" RESC1005X40N-0402-NOOVERLAY 95.973,64.586 r90 top
R7 "RESC1005X40N-0402-NOOVERLAY" RESC1005X40N-0402-NOOVERLAY 86.069,77.413 r0 top
R8 "RESC1005X40N-0402-NOOVERLAY" RESC1005X40N-0402-NOOVERLAY 93.232,69.107 r90 top
R9 "RESC1005X40N-0402-NOOVERLAY" RESC1005X40N-0402-NOOVERLAY 111.241,64.103 r270 top
R10 "RESC1005X40N-0402-NOOVERLAY" RESC1005X40N-0402-NOOVERLAY 112.384,60.928 r180 top
R11 "RESC1005X40N-0402-NOOVERLAY" RESC1005X40N-0402-NOOVERLAY 51.906,86.608 r90 top
R12 "RESC1005X40N-0402-NOOVERLAY" RESC1005X40N-0402-NOOVERLAY 57.062,86.608 r270 top
R13 "RESC1005X40N-0402-NOOVERLAY" RESC1005X40N-0402-NOOVERLAY 68.162,76.194 r90 top
R14 "RESC1005X40N-0402-NOOVERLAY" RESC1005X40N-0402-NOOVERLAY 35.549,83.103 r180 top
R15 "RESC1005X40N-0402-NOOVERLAY" RESC1005X40N-0402-NOOVERLAY 86.069,64.893 r0 top
R16 "RESC1005X40N-0402-NOOVERLAY" RESC1005X40N-0402-NOOVERLAY 65.063,77.159 r270 top
R17 "RESC1005X40N-0402-NOOVERLAY" RESC1005X40N-0402-NOOVERLAY 34.406,83.103 r0 top
R18 "RESC1005X40N-0402-NOOVERLAY" RESC1005X40N-0402-NOOVERLAY 86.044,67.202 r0 top
R19 "RESC1005X40N-0402-NOOVERLAY" RESC1005X40N-0402-NOOVERLAY 38.127,83.103 r0 top
R20 "RESC1005X40N-0402-NOOVERLAY" RESC1005X40N-0402-NOOVERLAY 39.067,83.103 r0 top
R21 "RESC1005X40N-0402-NOOVERLAY" RESC1005X40N-0402-NOOVERLAY 68.162,77.159 r90 top
R22 "RESC1005X40N-0402-NOOVERLAY" RESC1005X40N-0402-NOOVERLAY 93.994,86.582 r90 top
R23 "RESC1005X40N-0402-NOOVERLAY" RESC1005X40N-0402-NOOVERLAY 96.128,79.074 r270 top
R24 "RESC1005X40N-0402-NOOVERLAY" RESC1005X40N-0402-NOOVERLAY 39.333,57.804 r90 top
R25 "RESC1005X40N-0402-NOOVERLAY" RESC1005X40N-0402-NOOVERLAY 98.642,86.582 r90 top
R26 "RESC1005X40N-0402-NOOVERLAY" RESC1005X40N-0402-NOOVERLAY 39.333,56.153 r270 top
R27 "RESC2013X38N-0805-NOOVERLAY" RESC2013X38N-0805-NOOVERLAY 137.606,39.951 r90 top
R28 "RESC2013X38N-0805-NOOVERLAY" RESC2013X38N-0805-NOOVERLAY 137.479,55.648 r90 top
R29 "RESC2013X38N-0805-NOOVERLAY" RESC2013X38N-0805-NOOVERLAY 137.352,71.215 r90 top
R30 "RESC2013X38N-0805-NOOVERLAY" RESC2013X38N-0805-NOOVERLAY 142.508,36.53 r180 top
R31 "RESC2013X38N-0805-NOOVERLAY" RESC2013X38N-0805-NOOVERLAY 142.381,52.278 r180 top
R32 "RESC2013X38N-0805-NOOVERLAY" RESC2013X38N-0805-NOOVERLAY 142.279,67.945 r180 top
R33 "RESC1005X40N-0402-NOOVERLAY" RESC1005X40N-0402-NOOVERLAY 80.684,83.128 r0 top
R34 "RESC1005X40N-0402-NOOVERLAY" RESC1005X40N-0402-NOOVERLAY 81.65,83.128 r0 top
R35 "RESC1005X40N-0402-NOOVERLAY" RESC1005X40N-0402-NOOVERLAY 79.541,83.128 r180 top
R36 "RESC1005X40N-0402-NOOVERLAY" RESC1005X40N-0402-NOOVERLAY 82.767,83.128 r180 top
R37 "RESC2013X38N-0805-NOOVERLAY" RESC2013X38N-0805-NOOVERLAY 137.631,44.342 r90 top
R38 "RESC2013X38N-0805-NOOVERLAY" RESC2013X38N-0805-NOOVERLAY 137.682,59.938 r90 top
R39 "RESC2013X38N-0805-NOOVERLAY" RESC2013X38N-0805-NOOVERLAY 137.453,75.584 r90 top
R40 "RESC2013X38N-0805-NOOVERLAY" RESC2013X38N-0805-NOOVERLAY 141.67,44.342 r270 top
R41 "RESC2013X38N-0805-NOOVERLAY" RESC2013X38N-0805-NOOVERLAY 141.771,59.938 r270 top
R42 "RESC2013X38N-0805-NOOVERLAY" RESC2013X38N-0805-NOOVERLAY 141.543,75.584 r270 top
R43 "RES1508wide" RES1508wide 134.177,32.658 r90 top
R44 "RESC1508X55N-0603-NOOVERLAY" RESC1508X55N-0603-NOOVERLAY 112.493,45.88 r270 top
R45 "RESC1508X55N-0603-NOOVERLAY" RESC1508X55N-0603-NOOVERLAY 107.862,45.88 r270 top
R46 "RESC1508X55N-0603-NOOVERLAY" RESC1508X55N-0603-NOOVERLAY 96.61,46.806 r0 top
R47 "RESC1508X55N-0603-NOOVERLAY" RESC1508X55N-0603-NOOVERLAY 93.943,46.806 r180 top
R48 "RESC1508X55N-0603-NOOVERLAY" RESC1508X55N-0603-NOOVERLAY 112.467,47.72 r270 top
R49 "RESC1508X55N-0603-NOOVERLAY" RESC1508X55N-0603-NOOVERLAY 107.862,47.72 r270 top
R50 "RESC1508X55N-0603-NOOVERLAY" RESC1508X55N-0603-NOOVERLAY 98.693,32.353 r90 top
R51 "RESC1508X55N-0603-NOOVERLAY" RESC1508X55N-0603-NOOVERLAY 110.054,41.472 r270 top
R52 "RESC1508X55N-0603-NOOVERLAY" RESC1508X55N-0603-NOOVERLAY 106.262,26.816 r0 top
R53 "RESC2013X38N-0805-NOOVERLAY" RESC2013X38N-0805-NOOVERLAY 103.173,27.248 r90 top
R54 "RESC1508X55N-0603-NOOVERLAY" RESC1508X55N-0603-NOOVERLAY 102.401,43.098 r270 top
R55 "RESC1005X40N-0402-NOOVERLAY" RESC1005X40N-0402-NOOVERLAY 98.69,24.505 r270 top
R56 "RESC1508X55N-0603-NOOVERLAY" RESC1508X55N-0603-NOOVERLAY 100.877,36.671 r180 top
R57 "RESC1508X55N-0603-NOOVERLAY" RESC1508X55N-0603-NOOVERLAY 93.918,36.671 r180 top
R58 "RESC1508X55N-0603-NOOVERLAY" RESC1508X55N-0603-NOOVERLAY 103.113,36.671 r180 top
R59 "RESC1508X55N-0603-NOOVERLAY" RESC1508X55N-0603-NOOVERLAY 96.178,36.671 r0 top
R60 "RESC1508X55N-0603-NOOVERLAY" RESC1508X55N-0603-NOOVERLAY 98.363,36.671 r180 top
R61 "RESC1005X40N-0402-NOOVERLAY" RESC1005X40N-0402-NOOVERLAY 37.022,83.103 r180 top
R62 "RESC1005X40N-0402-NOOVERLAY" RESC1005X40N-0402-NOOVERLAY 40.171,83.103 r180 top
R63 "RESC1005X40N-0402-NOOVERLAY" RESC1005X40N-0402-NOOVERLAY 112.561,71.571 r90 top
R64 "RESC1005X40N-0402-NOOVERLAY" RESC1005X40N-0402-NOOVERLAY 76.493,24.251 r90 top
R65 "RESC1005X40N-0402-NOOVERLAY" RESC1005X40N-0402-NOOVERLAY 76.493,26.562 r90 top
R66 "RESC1005X40N-0402-NOOVERLAY" RESC1005X40N-0402-NOOVERLAY 84.974,24.251 r90 top
R67 "RESC1005X40N-0402-NOOVERLAY" RESC1005X40N-0402-NOOVERLAY 84.974,26.664 r90 top
R68 "RESC1005X40N-0402-NOOVERLAY" RESC1005X40N-0402-NOOVERLAY 93.765,24.251 r90 top
R69 "RESC1005X40N-0402-NOOVERLAY" RESC1005X40N-0402-NOOVERLAY 93.765,26.715 r90 top
R70 "RESC2013X38N-0805-NOOVERLAY" RESC2013X38N-0805-NOOVERLAY 137.631,46.552 r90 top
R71 "RESC2013X38N-0805-NOOVERLAY" RESC2013X38N-0805-NOOVERLAY 137.682,62.224 r90 top
R72 "RESC2013X38N-0805-NOOVERLAY" RESC2013X38N-0805-NOOVERLAY 137.453,77.87 r90 top
R73 "RESC1005X40N-0402-NOOVERLAY" RESC1005X40N-0402-NOOVERLAY 43.476,48.66 r270 top
R74 "RESC1005X40N-0402-NOOVERLAY" RESC1005X40N-0402-NOOVERLAY 42.584,35.706 r180 top
R75 "RESC1005X40N-0402-NOOVERLAY" RESC1005X40N-0402-NOOVERLAY 42.584,33.293 r180 top
R76 "RESC1005X40N-0402-NOOVERLAY" RESC1005X40N-0402-NOOVERLAY 42.584,30.702 r180 top
R77 "RESC2013X38N-0805-NOOVERLAY" RESC2013X38N-0805-NOOVERLAY 141.873,65.221 r270 top
R78 "RESC2013X38N-0805-NOOVERLAY" RESC2013X38N-0805-NOOVERLAY 139.79,31.795 r90 top
R79 "RESC2013X38N-0805-NOOVERLAY" RESC2013X38N-0805-NOOVERLAY 141.873,49.651 r270 top
R80 "RESC2013X38N-0805-NOOVERLAY" RESC2013X38N-0805-NOOVERLAY 141.873,33.827 r270 top
R81 "RESC1005X40N-0402-NOOVERLAY" RESC1005X40N-0402-NOOVERLAY 65.775,40.583 r0 top
R82 "RESC1005X40N-0402-NOOVERLAY" RESC1005X40N-0402-NOOVERLAY 75.085,40.278 r0 top
R83 "RESC1005X40N-0402-NOOVERLAY" RESC1005X40N-0402-NOOVERLAY 76.087,40.278 r0 top
R84 "RESC1005X40N-0402-NOOVERLAY" RESC1005X40N-0402-NOOVERLAY 90.743,39.618 r270 top
R85 "RESC1005X40N-0402-NOOVERLAY" RESC1005X40N-0402-NOOVERLAY 90.768,41.142 r270 top
R86 "RESC1005X40N-0402-NOOVERLAY" RESC1005X40N-0402-NOOVERLAY 78.449,83.128 r180 top
R87 "RESC1005X40N-0402-NOOVERLAY" RESC1005X40N-0402-NOOVERLAY 40.07,47.06 r90 top
R88 "RESC1005X40N-0402-NOOVERLAY" RESC1005X40N-0402-NOOVERLAY 40.07,44.495 r90 top
R89 "RESC1005X40N-0402-NOOVERLAY" RESC1005X40N-0402-NOOVERLAY 136.793,42.386 r270 top
RT1 "RESC1508X55N-0603-NOOVERLAY" RESC1508X55N-0603-NOOVERLAY 137.276,73.197 r90 top
SW1 "CAS-120TA-NoOverlay" CAS-120TA-NoOverlay 66.181,80.994 r90 top
SW2 "DIS02" DIS02 35.193,64.307 r180 top
SW3 "CAS-120TA-NoOverlay" CAS-120TA-NoOverlay 44.54,56.407 r90 top
T1 "TASTER_6x6_RED_r1" TASTER_6x6_RED_r1 33.364,56.052 r180 top
T2 "TASTER_SMD_SMALL-NoOverlay_r1" TASTER_SMD_SMALL-NoOverlay_r1 33.39,48.305 r0 top
TB1 "SCREW_TERMINAL-5.08-F-2" SCREW_TERMINAL-5.08-F-2 106.846,87.471 r0 top
TB2 "SCREW_TERMINAL_2.54_-_duplicate" SCREW_TERMINAL_2.54_-_duplicate 65.089,23.438 r0 top
TB3 "SCREW_TERMINAL_2.54_-_duplicate" SCREW_TERMINAL_2.54_-_duplicate 44.896,23.438 r0 top
TB4 "SCREW_TERMINAL_2.54_-_duplicate" SCREW_TERMINAL_2.54_-_duplicate 50.712,23.438 r0 top
TB5 "SCREW_TERMINAL_2.54_-_duplicate" SCREW_TERMINAL_2.54_-_duplicate 56.554,23.438 r0 top
TP1 "TEST_POINT_SMD-NoOverlay" TEST_POINT_SMD-NoOverlay 71.794,57.22 r90 top
TP2 "S1751-46R-NoOverlay" S1751-46R-NoOverlay 62.549,71.749 r0 top
TP3 "S1751-46R-NoOverlay" S1751-46R-NoOverlay 71.261,34.411 r0 top
TVS1 "TMP102" TMP102 81.178,80.859 r0 top
TVS2 "TMP102" TMP102 38.597,81.045 r0 top
U1 "HQFP50P700X700X100-48N" HQFP50P700X700X100-48N 66.283,49.117 r0 top
U2 "QFN50P700X700X100-49T500X500N-NoOverlay" QFN50P700X700X100-49T500X500N-NoOverlay 81.168,72.526 r0 top
U3 "SOT95P275X145-6L20N-SOT23-6-NoOverlay" SOT95P275X145-6L20N-SOT23-6-NoOverlay 110.199,67.609 r180 top
U4 "SOP65P640X120-16L25N-TSSOP16-NoOverlay" SOP65P640X120-16L25N-TSSOP16-NoOverlay 81.091,64.154 r180 top
U5 "SOP65P400X110-8L30N-TSSOP-8-NoOverlay" SOP65P400X110-8L30N-TSSOP-8-NoOverlay 103.163,30.321 r0 top
U6 "SOIC8P127_490X600X175L83X41N-SOIC8_-_NoOverlay" SOIC8P127_490X600X175L83X41N-SOIC8_-_NoOverlay 102.401,46.781 r180 top
U7 "SOT95P280X145-5L30N-SOT23-5-NoOverlay" SOT95P280X145-5L30N-SOT23-5-NoOverlay 108.929,36.646 r0 top
U8 "SOIC8P127_490X600X175L83X41N-SOIC8_-_NoOverlay" SOIC8P127_490X600X175L83X41N-SOIC8_-_NoOverlay 44.87,45.155 r0 top
U9 "SSOP-28-NoOverlay" SSOP-28-NoOverlay 38.622,74.848 r0 top
U10 "SON40P120X45_HS-9N" SON40P120X45_HS-9N 96.365,73.479 r0 top
Y1 "ABM3-NoOverlay" ABM3-NoOverlay 66.283,57.779 r180 top
Y2 "ABM3-NoOverlay" ABM3-NoOverlay 74.411,77.159 r270 top
? "CAPC1005X55N-0402-NoOverlay" CAPC1005X55N-0402-NoOverlay 79.033,79.826 r90 top

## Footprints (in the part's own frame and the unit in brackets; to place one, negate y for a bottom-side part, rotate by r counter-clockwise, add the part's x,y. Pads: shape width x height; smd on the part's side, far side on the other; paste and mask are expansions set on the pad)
ABM3-NoOverlay [mil] "KC00080BKP"
  round 7 smd paste-7 mask+0: 1(-80.71,0) 2(80.71,0)
CAPAE660X550D700DD185L260N [mil] "KC00080BKP"
  round 7 smd paste-7 mask+0: 1(-99.02,0) 2(99.02,0)
CAPC1005X55N-0402-NoOverlay [mil] "KC00080BKP"
  round 7 smd paste-7 mask+0: 1(0,18.9) 2(0,-18.9)
CAPC1608X55N-0603-NoOverlay [mil] "KC00080BKP"
  round 7 smd paste-7 mask+0: 1(0,29.53) 2(0,-29.53)
CAPC2013X100N-0805-NoOverlay [mil] "KC00080BKP"
  round 7 smd paste-7 mask+0: 1(0,35.43) 2(0,-35.43)
CAPC3216X140N-1206-NoOverlay [mil] "KC00080BKP"
  round 7 smd paste-7 mask+0: 1(-59.06,0) 2(59.06,0)
CAS-120TA-NoOverlay [mil] "KC00080BKP"
  round 7 smd paste-7 mask+0: 1(-43.31,68.9) 2(43.31,0) 3(-43.31,-68.9)
DIOGREENC2013X120N-0805-NoOverlay [mil] "KC00080BKP"
  round 7 smd paste-7 mask+0: 1(0,-35.44) 2(0,35.43)
DIOM5127X229N-SOD128-NoOverlay [mil] "KC00080BKP"
  round 7 smd paste-7 mask+0: 1(-86.61,0) 2(86.61,0)
DIOREDC2013X120N-0805-NoOverlay [mil] "KC00080BKP"
  round 7 smd paste-7 mask+0: 1(-35.43,0) 2(35.43,0)
DIOYELLOWC2013X120N-0805-NoOverlay [mil] "KC00080BKP"
  round 7 smd paste-7 mask+0: 1(-35.43,0) 2(35.43,0)
DIS02 [mil] "KC00080BKP"
  round 7 smd paste-7 mask+0: 1(-183.07,50) 2(-183.07,-50) 3(183.07,-50) 4(183.07,50)
HM1x2-NoOverlay [mil] "KC00080BKP"
  rect 65x65 hole 35 paste-73 mask+0: 1(-50,0)
  round 65 hole 35 paste-73 mask+0: 2(50,0)
HM1X16_-_Male [mil] "KC00080BKP"
  rect 65x65 hole 45 paste-73 mask+0: 1(0,750)
  round 65 hole 45 paste-73 mask+0: 2(0,650) 3(0,550) 4(0,450) 5(0,350) 6(0,250) 7(0,150) 8(0,50) 9(0,-50) 10(0,-150) 11(0,-250) 12(0,-350) 13(0,-450) 14(0,-550) 15(0,-650) 16(0,-750)
HM2X2 [mil] "KC00080BKP"
  rect 65x65 hole 39.37 paste-73 mask+0: 1(-50,50)
  round 65 hole 39.37 paste-73 mask+0: 2(50,50) 3(-50,-50) 4(50,-50)
HM2X3 [mil] "KC00080BKP"
  rect 65x65 hole 39.37 paste-73 mask+0: 1(-50,100)
  round 65 hole 39.37 paste-73 mask+0: 2(50,100) 3(-50,0) 4(50,0) 5(-50,-100) 6(50,-100)
HM2X4-NoOverlay [mm] "KC00080BKP"
  rect 1.5x1.5 hole 0.9 paste-1.703 mask+0: 1(-1.27,3.81)
  round 1.5 hole 0.9 paste-1.703 mask+0: 2(1.27,3.81) 3(-1.27,1.27) 4(1.27,1.27) 5(-1.27,-1.27) 6(1.27,-1.27) 7(-1.27,-3.81) 8(1.27,-3.81)
HM2X5-NoOverlay [mm] "KC00080BKP"
  rect 1.5x1.5 hole 0.9 paste-1.703 mask+0: 1(-1.27,5.08)
  round 1.5 hole 0.9 paste-1.703 mask+0: 2(1.27,5.08) 3(-1.27,2.54) 4(1.27,2.54) 5(-1.27,0) 6(1.27,0) 7(-1.27,-2.54) 8(1.27,-2.54) 9(-1.27,-5.08) 10(1.27,-5.08)
HM2X5-SMD-1.27 [mm] "KC00080BKP"
  rect 1.9x0.74 smd paste-2.052 mask+0: 1(-2.125,2.54) 2(2.125,2.54) 3(-2.125,1.27) 4(2.125,1.27) 5(-2.125,0) 6(2.125,0) 7(-2.125,-1.27) 8(2.125,-1.27) 9(-2.125,-2.54) 10(2.125,-2.54)
HM254P2x20-SMD [mil] "KC00080BKP"
  round 7 smd paste-7 mask+0: 1(-107.48,950) 2(107.48,950) 3(-107.48,850) 4(107.48,850) 5(-107.48,750) 6(107.48,750) 7(-107.48,650) 8(107.48,650) 9(-107.48,550) 10(107.48,550) 11(-107.48,450) 12(107.48,450) 13(-107.48,350) 14(107.48,350) 15(-107.48,250) 16(107.48,250) 17(-107.48,150) 18(107.48,150) 19(-107.48,50) 20(107.48,50) 21(-107.48,-50) 22(107.48,-50) 23(-107.48,-150) 24(107.48,-150) 25(-107.48,-250) 26(107.48,-250) 27(-107.48,-350) 28(107.48,-350) 29(-107.48,-450) 30(107.48,-450) 31(-107.48,-550) 32(107.48,-550) 33(-107.48,-650) 34(107.48,-650) 35(-107.48,-750) 36(107.48,-750) 37(-107.48,-850) 38(107.48,-850) 39(-107.48,-950) 40(107.48,-950)
HQFP50P700X700X100-48N [mm] "KC00080BKP"
  round 0.178 smd paste-0.178 mask+0: 1(-4.175,2.75) 2(-4.175,2.25) 3(-4.175,1.75) 4(-4.175,1.25) 5(-4.175,0.75) 6(-4.175,0.25) 7(-4.175,-0.25) 8(-4.175,-0.75) 9(-4.175,-1.25) 10(-4.175,-1.75) 11(-4.175,-2.25) 12(-4.175,-2.75) 13(-2.75,-4.175) 14(-2.25,-4.175) 15(-1.75,-4.175) 16(-1.25,-4.175) 17(-0.75,-4.175) 18(-0.25,-4.175) 19(0.25,-4.175) 20(0.75,-4.175) 21(1.25,-4.175) 22(1.75,-4.175) 23(2.25,-4.175) 24(2.75,-4.175) 25(4.175,-2.75) 26(4.175,-2.25) 27(4.175,-1.75) 28(4.175,-1.25) 29(4.175,-0.75) 30(4.175,-0.25) 31(4.175,0.25) 32(4.175,0.75) 33(4.175,1.25) 34(4.175,1.75) 35(4.175,2.25) 36(4.175,2.75) 37(2.75,4.175) 38(2.25,4.175) 39(1.75,4.175) 40(1.25,4.175) 41(0.75,4.175) 42(0.25,4.175) 43(-0.25,4.175) 44(-0.75,4.175) 45(-1.25,4.175) 46(-1.75,4.175) 47(-2.25,4.175) 48(-2.75,4.175)
  rect 4.5x4.5 smd paste-4.6 mask+0: 49(0,0)
IND_8x8x4-NoOverlay [mil] "KC00080BKP"
  round 7 smd paste-7 mask+0: 1(-110.24,0) 2(110.24,0)
INDC1608X95N-0603-NOOVERLAY [mil] "KC00080BKP"
  round 7 smd paste-7 mask+0: 1(-31.5,0) 2(31.5,0)
INDC2213X140N-0805-NOOVERLAY [mil] "KC00080BKP"
  round 7 smd paste-7 mask+0: 1(-39.37,0) 2(39.37,0)
JUMPER-FLD2X3 [mil] "KC00080BKP"
  rect 65x65 hole 35 paste-73 mask+0: 1(0,0)
  round 65 hole 35 paste-73 mask+0: 2(100,0) 3(0,-100) 4(100,-100) 5(0,-200) 6(100,-200)
N6R [mil] "KC00080BKP"
  round 7 smd paste-7 mask+0: 1(-77.76,-179.13) 2(0,179.13) 3(77.76,-179.13)
QFN50P700X700X100-49T500X500N-NoOverlay [mm] "KC00080BKP"
  round 0.178 smd paste-0.178 mask+0: 1(-3.43,2.75) 2(-3.43,2.25) 3(-3.43,1.75) 4(-3.43,1.25) 5(-3.43,0.75) 6(-3.43,0.25) 7(-3.43,-0.25) 8(-3.43,-0.75) 9(-3.43,-1.25) 10(-3.43,-1.75) 11(-3.43,-2.25) 12(-3.43,-2.75) 13(-2.75,-3.43) 14(-2.25,-3.43) 15(-1.75,-3.43) 16(-1.25,-3.43) 17(-0.75,-3.43) 18(-0.25,-3.43) 19(0.25,-3.43) 20(0.75,-3.43) 21(1.25,-3.43) 22(1.75,-3.43) 23(2.25,-3.43) 24(2.75,-3.43) 25(3.43,-2.75) 26(3.43,-2.25) 27(3.43,-1.75) 28(3.43,-1.25) 29(3.43,-0.75) 30(3.43,-0.25) 31(3.43,0.25) 32(3.43,0.75) 33(3.43,1.25) 34(3.43,1.75) 35(3.43,2.25) 36(3.43,2.75) 37(2.75,3.43) 38(2.25,3.43) 39(1.75,3.43) 40(1.25,3.43) 41(0.75,3.43) 42(0.25,3.43) 43(-0.25,3.43) 44(-0.75,3.43) 45(-1.25,3.43) 46(-1.75,3.43) 47(-2.25,3.43) 48(-2.75,3.43)
  rect 5x5 smd paste-5 mask+0: 49(0,0)
RES1508wide [mil] "KC00080BKP"
  round 7 smd paste-7 mask+0: 1(-37.4,0) 2(37.4,0)
RESC1005X40N-0402-NOOVERLAY [mil] "KC00080BKP"
  round 7 smd paste-7 mask+0: 1(0,18.9) 2(0,-18.9)
RESC1508X55N-0603-NOOVERLAY [mil] "KC00080BKP"
  round 7 smd paste-7 mask+0: 1(0,32.29) 2(0,-32.29)
RESC2013X38N-0805-NOOVERLAY [mil] "KC00080BKP"
  round 7 smd paste-7 mask+0: 1(0,39.37) 2(0,-39.37)
S1751-46R-NoOverlay [mil] "KC00080BKP"
  round 7 smd paste-7 mask+0: 1(0,0)
SCREW_TERMINAL-5.08-F-2 [mil] "KC00080BKP"
  round 110 hole 55 paste-118 mask+0: 1(-100,0) 2(100,0)
SCREW_TERMINAL_2.54_-_duplicate [mm] "KC00080BKP"
  round 1.8 hole 1 paste-2.003 mask+0: 1(-1.27,0) 2(1.27,0)
SCREW_TERMINAL_3P_5.08 [mm] "KC00080BKP"
  rect 1.65x1.65 hole 1.1 paste-1.853 mask+0: 1(-5.08,0)
  round 1.65 hole 1.1 paste-1.853 mask+0: 2(0,0) 3(5.08,0)
SFLAT300P360X150X100-2N [mil] "KC00080BKP"
  round 7 smd paste-7 mask+0: 1(-62.99,0) 2(62.99,0)
SOD3716X135N-NoOverlay [mil] "KC00080BKP"
  round 7 smd paste-7 mask+0: 1(-70.87,0) 2(70.87,0)
SOIC8P127_490X600X175L83X41N-SOIC8_-_NoOverlay [mil] "KC00080BKP"
  round 7 smd paste-7 mask+0: 1(-96.65,75) 2(-96.65,25) 3(-96.65,-25) 4(-96.65,-75) 5(96.65,-75) 6(96.65,-25) 7(96.65,25) 8(96.65,75)
SON40P120X45_HS-9N [mm] "KC00080BKP"
  rect 0.35x0.26 smd paste-0.45 mask+0: 1(-0.55,0.6) 2(-0.55,0.2) 3(-0.55,-0.2) 4(-0.55,-0.6) 5(0.55,-0.6) 6(0.55,-0.2) 7(0.55,0.2) 8(0.55,0.6)
  rect 0.4x1.44 smd paste-1.54 mask+0: 9(0,0)
SOP65P400X110-8L30N-TSSOP-8-NoOverlay [mm] "KC00080BKP"
  round 0.178 smd paste-0.178 mask+0: 1(-1.655,0.975) 2(-1.655,0.325) 3(-1.655,-0.325) 4(-1.655,-0.975) 5(1.655,-0.975) 6(1.655,-0.325) 7(1.655,0.325) 8(1.655,0.975)
SOP65P640X120-16L25N-TSSOP16-NoOverlay [mm] "KC00080BKP"
  round 0.178 smd paste-0.178 mask+0: 1(-2.87,2.275) 2(-2.87,1.625) 3(-2.87,0.975) 4(-2.87,0.325) 5(-2.87,-0.325) 6(-2.87,-0.975) 7(-2.87,-1.625) 8(-2.87,-2.275) 9(2.87,-2.275) 10(2.87,-1.625) 11(2.87,-0.975) 12(2.87,-0.325) 13(2.87,0.325) 14(2.87,0.975) 15(2.87,1.625) 16(2.87,2.275)
SOT65P210X100-3N-NoOverlay [mil] "KC00080BKP"
  round 7 smd paste-7 mask+0: 1(-41.34,25.59) 2(-41.34,-25.59) 3(41.34,0)
SOT95P240X110-3N-NoOverlay [mil] "KC00080BKP"
  round 7 smd paste-7 mask+0: 1(-45.28,37.4) 2(-45.28,-37.4) 3(45.28,0)
SOT95P275X145-6L20N-SOT23-6-NoOverlay [mil] "KC00080BKP"
  round 7 smd paste-7 mask+0: 1(-48.82,37.4) 2(-48.82,0) 3(-48.82,-37.4) 4(48.82,-37.4) 5(48.82,0) 6(48.82,37.4)
SOT95P280X145-5L30N-SOT23-5-NoOverlay [mil] "KC00080BKP"
  round 7 smd paste-7 mask+0: 1(-49.41,37.4) 2(-49.41,0) 3(-49.41,-37.4) 4(49.41,-37.4) 5(49.41,37.4)
SSOP-28-NoOverlay [mil] "KC00080BKP"
  round 7 smd paste-7 mask+0: 1(-138.78,166.42) 2(-138.78,140.82) 3(-138.78,115.22) 4(-138.78,89.62) 5(-138.78,64.02) 6(-138.78,38.42) 7(-138.78,12.82) 8(-138.78,-12.78) 9(-138.78,-38.38) 10(-138.78,-63.98) 11(-138.78,-89.58) 12(-138.78,-115.18) 13(-138.78,-140.78) 14(-138.78,-166.42) 15(138.78,-166.42) 16(138.78,-140.78) 17(138.78,-115.18) 18(138.78,-89.58) 19(138.78,-63.98) 20(138.78,-38.38) 21(138.78,-12.78) 22(138.78,12.82) 23(138.78,38.42) 24(138.78,64.02) 25(138.78,89.62) 26(138.78,115.22) 27(138.78,140.82) 28(138.78,166.42)
TASTER_6x6_RED_r1 [mm] "KC00080BKP"
  rect 1.27x1.27 smd paste-1.473 mask+0: 1(-3.75,2.25) 2(-3.75,-2.25) 3(3.75,-2.25) 4(3.75,2.25)
TASTER_SMD_SMALL-NoOverlay_r1 [mm] "KC00080BKP"
  rect 1.27x1.27 smd paste-1.473 mask+0: 1(-2.921,1.5) 2(-2.921,-1.5) 3(2.921,-1.5) 4(2.921,1.5)
TC2030NL_r1 [mil] "KC00080BKP"
  round 31 smd paste-39 mask+0: 1(-50,-25) 2(-50,25) 3(0,-25) 4(0,25) 5(50,-25) 6(50,25)
  round 34.65 hole 34.65 unplated paste-42.65 mask+0: 7(100,-40) 8(100,40) 9(-100,0)
TEST_POINT_SMD-NoOverlay [mm] "KC00080BKP"
  round 0.9 smd paste-1.103 mask+0: 1(0,0)
TMP102 [mm] "KC00080BKP"
  rect 0.45x0.3 smd paste-0.55 mask+0: 1(-0.675,0.5) 2(-0.675,0) 3(-0.675,-0.5) 4(0.675,-0.5) 5(0.675,0) 6(0.675,0.5)
TSOP6F95P220X290X80-6N [mil] "KC00080BKP"
  round 7 smd paste-7 mask+0: 1(-37.4,-51.18) 2(0,-51.18) 3(37.4,-51.18) 4(37.4,51.18) 5(0,51.18) 6(-37.4,51.18)
USB-C_SMD_16P-NoOverlay_r1 [mm] "KC00080BKP"
  round 0.178 smd paste-0.178 mask+0: 1(-5.11,-2.275) 2(-5.11,1.625) 3(5.11,1.625) 4(5.11,-2.275) A1B12(-3.2,2.2) A4B9(-2.4,2.2) A5(-1.25,2.2) A6(-0.25,2.2) A7(0.25,2.2) A8(1.25,2.2) B1A12(3.2,2.2) B4A9(2.4,2.2) B5(1.75,2.2) B6(0.75,2.2) B7(-0.75,2.2) B8(-1.75,2.2)
  round 0 hole 0.65 unplated paste-0.65 mask+0: 5(-2.89,1.125) 6(2.89,1.125)
XCUZ230P125X250X100-2N [mil] "KC00080BKP"
  round 7 smd paste-7 mask+0: 1(-45.28,0) 2(45.28,0)

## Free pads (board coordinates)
  round 0.6 smd paste-1.4 mask+0: ""(28.564,27.502)
  round 0.406 smd paste-0.406 mask+0: ""(30.543,62.783)
  round 0.254 smd paste-0.254 mask+0: ""(93.918,35.851) ""(98.363,37.492)

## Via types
v1: diameter 0.406, hole 0.203, TOP to BOTTOM, tented both sides, 533 vias
v2: diameter 6, hole 4.2, TOP to BOTTOM, 4 vias
v3: diameter 1.651, hole 1, TOP to BOTTOM, 1 vias

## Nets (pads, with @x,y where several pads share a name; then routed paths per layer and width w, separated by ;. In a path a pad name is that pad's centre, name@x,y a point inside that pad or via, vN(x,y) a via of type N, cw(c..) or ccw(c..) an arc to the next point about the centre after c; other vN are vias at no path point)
ADIN: C55.2 J33.1 R47.2 | length 10.8
  TOP w0.406: J33.1@83.58,46.73 84.531,47.681 C55.2@90.819,47.681 90.874,47.626 R47.2@93.943,47.626
BOOT: J2.2 R7.2 U2.37 | length 9.4
  TOP w0.254: U2.37@83.918,75.956 85.092,75.956 R7.2@86.069,76.933 87.822,75.18 87.822,74.416 90.362,71.876 J2.2@90.413,71.876
CC1_1: CN3.A5 R62.2 | length 2.1
  TOP w0.203: CN3.A5@39.847,85.544 39.847,83.907 R62.2@40.171,83.583
CC1_2: CN2.A5 R36.2 | length 2.1
  TOP w0.254: CN2.A5@82.442,85.576 82.442,83.933 R36.2@82.767,83.608
CC2_1: CN3.B5 R61.2 | length 2
  TOP w0.203: CN3.B5@36.847,85.544 36.847,83.758 R61.2@37.022,83.583
CC2_2: CN2.B5 R35.2 | length 2
  TOP w0.254: CN2.B5@79.442,85.576 79.442,83.707 R35.2@79.541,83.608
COM: J5.33 U1.26 | length 59.4
  TOP w0.254: v1(69.381,46.806) 69.443,46.867 U1.26@70.458,46.867 ; v1(117.819,38.018) 118.708,38.907
  Mid-Layer 1 w0.254: v1(69.381,39.059) 72.887,39.059 74.461,37.484 117.286,37.484 v1(117.819,38.018)
  Mid-Layer 2 w0.254: v1(69.381,39.059) v1(69.381,46.806)
COM_IND: LD4.1 U2.17 | length 38.9
  TOP w0.254: v1(80.418,68.218) U2.17@80.418,69.096 ; v1(96.763,88.716) 97.742,89.696 LD4.1@97.742,89.808
  Mid-Layer 1 w0.254: v1(80.888,88.716) v1(96.763,88.716)
  Mid-Layer 2 w0.254: v1(80.418,68.218) 80.888,68.688 v1(80.888,88.716)
COM_INT: J5.34 R78.1 | length 16.2
  TOP w0.254: 126.303,38.907 127.034,38.175 v1(127.096,38.175) ; R78.1@138.79,31.795 v1(138.79,32.82)
  Mid-Layer 2 w0.254: v1(127.096,38.175) 133.74,38.175 138.79,33.125 v1(138.79,32.82)
CS: J17.7 R87.2 U8.1 | length 15.3
  TOP w0.254: R87.2@40.55,47.06 U8.1@42.415,47.06 43.118,47.06 v1(43.588,46.59)
  Mid-Layer 1 w0.254: v1(43.588,46.59) 43.575,46.577 43.575,45.206 46.039,42.742 53.049,42.742 J17.7@53.202,42.894
CURR_OFFSET_2V5: R51.1 U7.3 U7.4 | length 9.4
  TOP w0.254: U7.3@107.674,35.696 U7.4@110.133,35.696 ; U7.4@110.184,35.696 U7.4@110.133,35.696 ; R51.1@110.874,41.472 109.132,39.73 109.132,36.697 U7.4@110.133,35.696
DAPEN: J2.5 R18.2 U2.29 | length 8.7
  TOP w0.254: U2.29@84.598,71.776 85.458,71.776 v1(85.866,71.368) ; R18.2@86.044,66.722 87.799,66.722 J2.5@87.873,66.796
  Mid-Layer 2 w0.254: v1(85.866,71.368) 86.679,70.555 86.679,68.04 87.873,66.847 J2.5@87.873,66.796
DBGO: J13.1 J13.3 J13.5 J18.1 | length 12.6
  Mid-Layer 2 w0.254: J13.1@32.247,35.732 J13.3@32.247,33.192 J13.5@32.247,30.652 32.247,23.438 J18.1@32.45,23.235
DIR: J11.1 J11.3 SW3.2 | length 11.4
  TOP w0.254: SW3.2@44.54,57.507 44.54,57.601 44.947,58.007 J11.1@53.176,58.007 J11.3@53.176,55.467
EXT-PRG-EN: R16.1 SW1.2 U4.8 | length 34.1
  TOP w0.254: R16.1@65.543,77.159 65.698,77.314 v1(65.698,77.667) 65.698,81.375 66.181,81.858 SW1.2@66.181,82.094 ; v1(82.691,66.429) U4.8@83.961,66.429
  Mid-Layer 1 w0.254: v1(65.698,67.532) 69.839,67.532 70.942,66.429 v1(82.691,66.429)
  Mid-Layer 2 w0.254: v1(65.698,67.532) v1(65.698,77.667)
G_HS_U: J5.26 R27.1 | length 14.2
  TOP w0.254: 126.303,49.067 127.034,48.335 v1(127.096,48.335) ; v1(135.929,40.812) 136.606,40.135 R27.1@136.606,39.951
  Mid-Layer 2 w0.254: v1(127.096,48.335) 128.406,48.335 v1(135.929,40.812)
G_HS_V: J5.20 R28.1 | length 11.7
  TOP w0.254: J5.20@125.197,56.687 126.103,56.687 127.141,55.648 R28.1@136.479,55.648
G_HS_W: J5.14 R29.1 | length 14.1
  TOP w0.254: J5.14@125.197,64.307 129.503,64.307 136.352,71.155 R29.1@136.352,71.215
G_LS_U: J5.22 R37.1 | length 14.3
  TOP w0.254: 126.303,54.147 127.034,53.415 v1(127.096,53.415) ; v1(135.955,45.203) 136.631,44.526
  Mid-Layer 2 w0.254: v1(127.096,53.415) 127.742,53.415 v1(135.955,45.203)
G_LS_V: J5.16 R38.1 | length 11.1
  TOP w0.254: 126.303,61.767 127.034,61.035 v1(127.096,61.035) ; v1(135.904,59.938) R38.1@136.682,59.938
  BOTTOM w0.254: v1(127.096,61.035) 134.806,61.035 v1(135.904,59.938)
G_LS_W: J5.10 R39.1 | length 18.5
  TOP w0.254: J5.10@125.197,69.387 126.15,69.387 126.735,68.802 v1(126.735,68.472) ; v1(133.326,72.524) 136.387,75.584 R39.1@136.453,75.584
  BOTTOM w0.254: v1(126.735,68.472) 132.018,68.472 134.888,71.342 134.888,72.282 134.558,72.612 133.415,72.612 v1(133.326,72.524)
GHU: J5.25 U1.17 | length 58.5
  TOP w0.254: v1(65.533,43.746) U1.17@65.533,44.942 ; v1(117.819,48.178) 118.708,49.067
  Mid-Layer 1 w0.254: v1(65.533,43.746) 67.781,41.497 76.925,41.497 79.745,44.317 113.984,44.317 117.845,48.178 v1@117.845,48.254
GHV: J5.19 U1.15 | length 59.9
  TOP w0.254: U1.15@64.533,44.942 v1(64.533,46.349) ; v1(117.819,55.798) 118.708,56.687
  Mid-Layer 1 w0.254: v1(64.533,46.349) 65.498,47.314 79.186,47.314 80.176,48.305 110.326,48.305 117.768,55.747 v1@117.87,55.747
GHW: J5.13 U1.13 | length 82.8
  TOP w0.254: v1(63.171,43.974) 63.533,44.335 U1.13@63.533,44.942 ; v1(117.87,65.246) 117.87,65.221 118.784,64.307 J5.13@119.737,64.307
  Mid-Layer 1 w0.254: v1(64.2,66.872) 64.555,66.516 68.492,66.516 70.22,64.789 91.479,64.789 92.978,66.288 116.829,66.288 v1@117.845,65.272
  Mid-Layer 2 w0.254: v1(63.171,43.974) 62.473,44.672 62.473,52.267 63.971,53.766 63.971,66.643 v1(64.2,66.872)
GLU: J5.21 U1.18 | length 57.7
  TOP w0.254: v1(66.029,46.12) 66.033,46.116 U1.18@66.033,44.942 ; v1(117.819,53.258) 118.708,54.147
  Mid-Layer 1 w0.254: v1(66.029,46.12) 78.144,46.12 78.805,45.46 89.193,45.46 89.879,46.146 110.707,46.146 v1(117.819,53.258)
GLV: J5.15 U1.16 | length 65
  TOP w0.254: U1.16@65.033,44.942 65.033,46.115 v1(65.267,46.349) ; v1(117.895,60.979) 118.683,61.767
  Mid-Layer 1 w0.254: v1(73.242,58.612) 77.403,58.612 79.999,61.208 86.145,61.208 86.374,60.979 v1(117.895,60.979)
  Mid-Layer 2 w0.254: v1(65.267,46.349) 65.267,47.416 68.315,50.464 69.94,50.464 73.242,53.766 v1(73.242,58.612)
GLW: J5.9 U1.14 | length 85.5
  TOP w0.254: v1(63.565,43.504) 64.033,43.972 U1.14@64.033,44.942 ; v1(117.819,68.498) 118.708,69.387
  Mid-Layer 1 w0.254: v1(63.514,67.609) 64.479,67.609 65.114,66.974 69.592,66.974 71.243,65.323 90.971,65.323 93.816,68.167 95.442,68.167 96.026,68.752 117.565,68.752 v1(117.819,68.498)
  Mid-Layer 2 w0.254: v1(63.514,67.609) 63.514,54.197 61.939,52.623 61.939,44.444 62.93,43.453 v1@63.565,43.453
